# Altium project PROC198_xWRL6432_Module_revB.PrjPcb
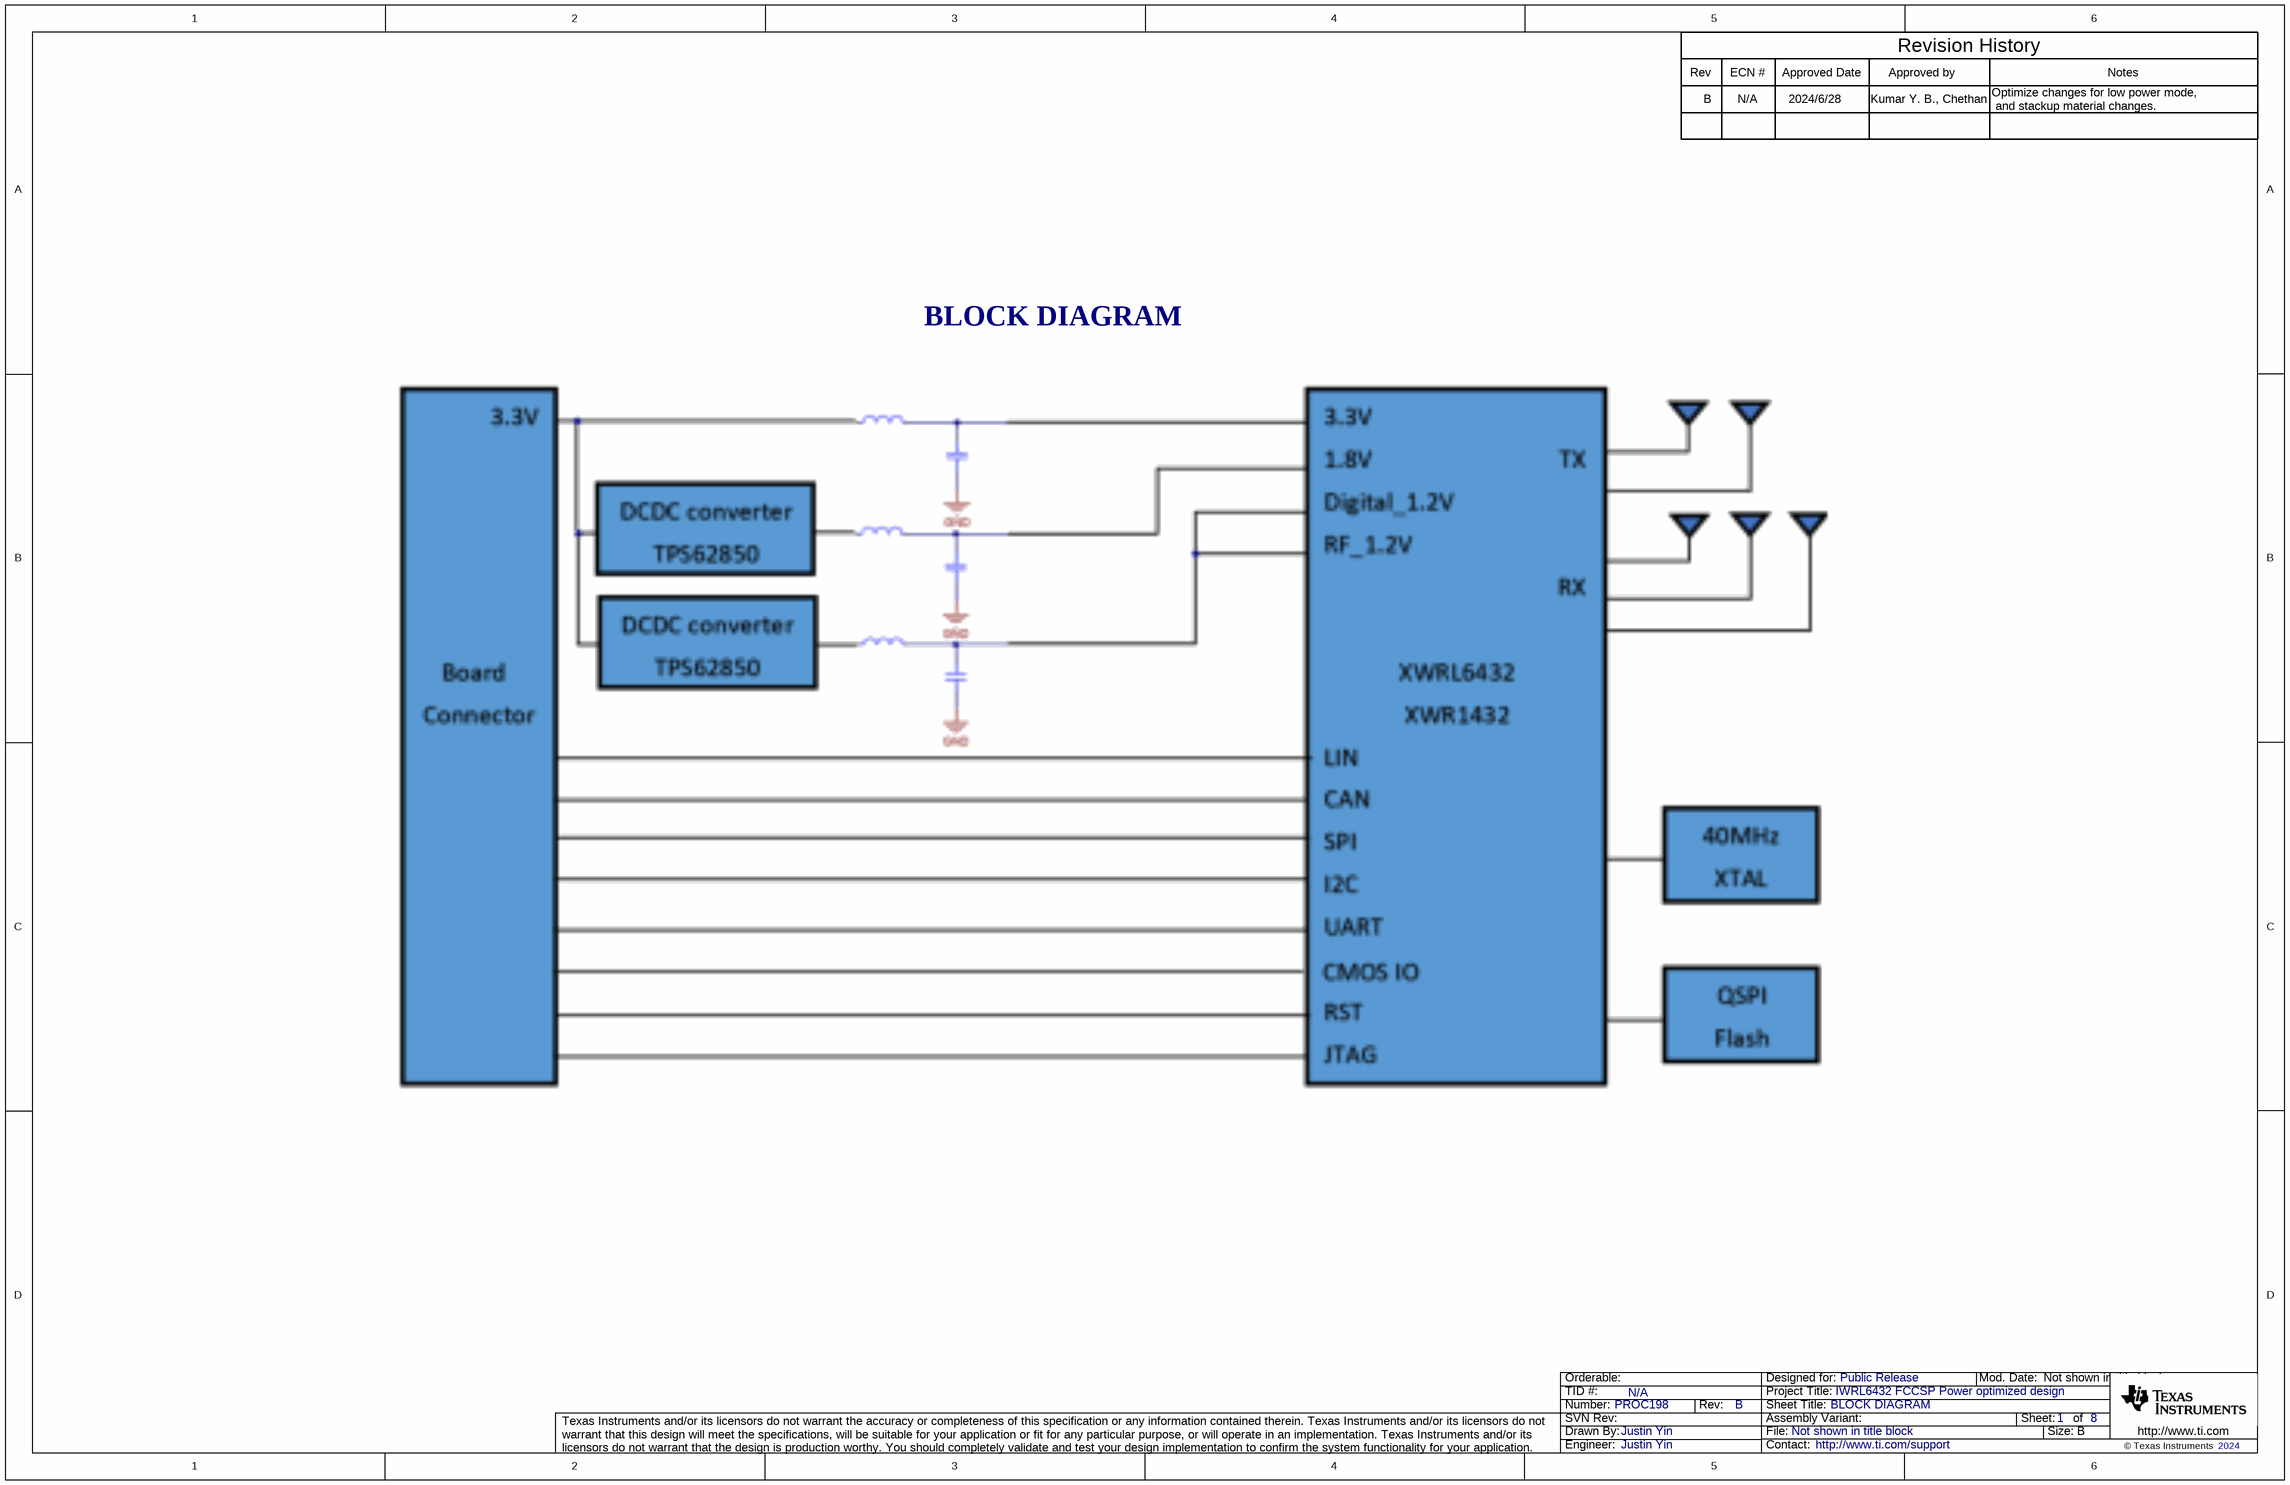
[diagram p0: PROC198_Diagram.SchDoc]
CopyrightYear: 2024; PCB_Layout: Justin Yin; PCB_Rev: B; PRJ_Customer: Public Release; PRJ_Engineer: Justin Yin; PRJ_Number: PROC198; PRJ_Title: IWRL6432 FCCSP Power optimized design; SCH_Rev: B; TechSupport: http://www.ti.com/support; TID: N/A
8 sheets, 117 parts. Net scope: flat (ports and power ports of the same name join across sheets).
Board file: PROC198_PCB.PcbDoc
Sheets:
  PROC198_Diagram.SchDoc
  PROC198_Table_Of_Contents.SchDoc
  PROC198_PWR_Connector.SchDoc
  PROC198_DC_Regulators.SchDoc
  PROC198_xWRL6432_Chip.SchDoc
  PROC198_Decoupling_caps.SchDoc
  PROC198_QSPI_Flash.SchDoc
  PROC198_Hardware.SchDoc

## Sheet PROC198_Diagram.SchDoc: BLOCK DIAGRAM
size 431 x 279 mm; Date: Not shown in title block; ApprovedBy: Not shown in title block; CheckedBy: Not shown in title block; Author: Not shown in title block; CompanyName: Not shown in title block; DrawnBy: Justin Yin; Organization: Not shown in title block; Address1: Not shown in title block; Address2: Not shown in title block; Address3: Not shown in title block; Address4: Not shown in title block; DocumentNumber: 1; Revision: Use project parameter SCH_Rev; SheetNumber: 1; SheetTotal: 8; PageSetup: Record=PageOptions¦CenterHorizontal=True¦CenterVertical=True¦PrintScale=1.00¦XCorrection=1.00¦YCorrection=1.00¦PrintKind=0¦BorderSize=5000000¦LeftOffset=0¦BottomOffset=0¦Orientation=2¦PaperLength=1000¦PaperWidth=1000¦Scale=100¦PaperSource=15¦PrintQuality=600¦MediaType=1¦DitherType=10¦PaperKind=Letter¦PrintScaleMode=1

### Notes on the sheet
- Rev
- B
- ECN #
- N/A
- 2024/6/28
- Approved Date
- Approved by
- Kumar Y. B., Chethan
- Revision History
- Optimize changes for low power mode,
- Notes
- and stackup material changes.
- BLOCK DIAGRAM

## Sheet PROC198_Table_Of_Contents.SchDoc: TABLE OF CONTENTS
size 431 x 279 mm; Date: Not shown in title block; ApprovedBy: Not shown in title block; CheckedBy: Not shown in title block; Author: Not shown in title block; CompanyName: Not shown in title block; DrawnBy: Justin Yin; Engineer: Not shown in title block; Organization: Not shown in title block; Address1: Not shown in title block; Address2: Not shown in title block; Address3: Not shown in title block; Address4: Not shown in title block; DocumentNumber: 2; Revision: Use project parameter SCH_Rev; SheetNumber: 2; SheetTotal: 8; PageSetup: Record=PageOptions¦CenterHorizontal=True¦CenterVertical=True¦PrintScale=1.00¦XCorrection=1.00¦YCorrection=1.00¦PrintKind=0¦BorderSize=5000000¦LeftOffset=0¦BottomOffset=0¦Orientation=2¦PaperLength=1000¦PaperWidth=1000¦Scale=100¦PaperSource=15¦PrintQuality=600¦MediaType=1¦DitherType=10¦PaperKind=Letter¦PrintScaleMode=1
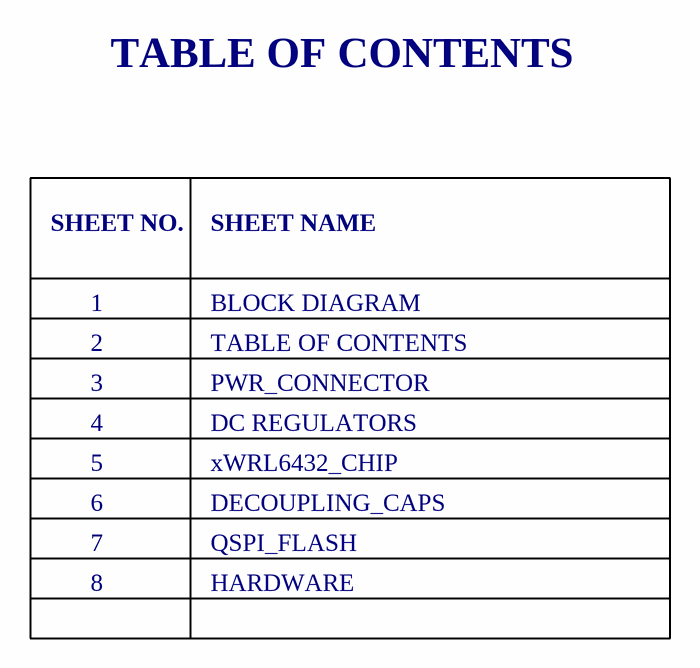
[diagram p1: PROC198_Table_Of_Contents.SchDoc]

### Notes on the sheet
- TABLE OF CONTENTS
- SHEET NO.
- SHEET NAME
- 1
- 2
- 3
- BLOCK DIAGRAM
- PWR_CONNECTOR
- 4
- 5
- DC REGULATORS
- xWRL6432_CHIP
- 7
- 8
- 6
- DECOUPLING_CAPS
- QSPI_FLASH
- HARDWARE

## Sheet PROC198_PWR_Connector.SchDoc: PWR_Connector
size 431 x 279 mm; Date: Not shown in title block; ApprovedBy: Not shown in title block; CheckedBy: Not shown in title block; Author: Not shown in title block; CompanyName: Not shown in title block; DrawnBy: Justin Yin; Engineer: Not shown in title block; Organization: Not shown in title block; Address1: Not shown in title block; Address2: Not shown in title block; Address3: Not shown in title block; Address4: Not shown in title block; DocumentNumber: 3; Revision: Use project parameter SCH_Rev; SheetNumber: 3; SheetTotal: 8; PageSetup: Record=PageOptions¦CenterHorizontal=True¦CenterVertical=True¦PrintScale=1.00¦XCorrection=1.00¦YCorrection=1.00¦PrintKind=0¦BorderSize=5000000¦LeftOffset=0¦BottomOffset=0¦Orientation=2¦PaperLength=1000¦PaperWidth=1000¦Scale=100¦PaperSource=15¦PrintQuality=600¦MediaType=1¦DitherType=10¦PaperKind=Letter¦PrintScaleMode=1
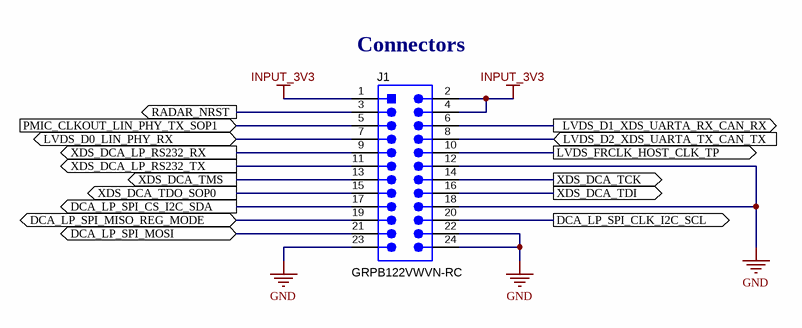
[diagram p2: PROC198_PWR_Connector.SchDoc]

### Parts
J1  GRPB122VWVN-RC  [Sullins_GRPB122VWVN]

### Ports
DCA_LP_SPI_CLK_I2C_SCL (out), DCA_LP_SPI_CS_I2C_SDA (out), DCA_LP_SPI_MISO_REG_MODE (bidir), DCA_LP_SPI_MOSI (bidir), LVDS_D0_LIN_PHY_RX (bidir), LVDS_D1_XDS_UARTA_RX_CAN_RX (out), LVDS_D2_XDS_UARTA_TX_CAN_TX (in), LVDS_FRCLK_HOST_CLK_TP (out), PMIC_CLKOUT_LIN_PHY_TX_SOP1 (in), RADAR_NRST (out), XDS_DCA_LP_RS232_RX (out), XDS_DCA_LP_RS232_TX (out), XDS_DCA_TCK (out), XDS_DCA_TDI (out), XDS_DCA_TDO_SOP0 (out), XDS_DCA_TMS (out)

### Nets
GND: J1.12 J1.18 J1.22 J1.23 J1.24
INPUT_3V3: J1.1 J1.2 J1.4
DCA_LP_SPI_CLK_I2C_SCL: J1.20 ; port DCA_LP_SPI_CLK_I2C_SCL
DCA_LP_SPI_CS_I2C_SDA: J1.17 ; port DCA_LP_SPI_CS_I2C_SDA
DCA_LP_SPI_MISO_REG_MODE: J1.19 ; port DCA_LP_SPI_MISO_REG_MODE
DCA_LP_SPI_MOSI: J1.21 ; port DCA_LP_SPI_MOSI
LVDS_D0_LIN_PHY_RX: J1.7 ; port LVDS_D0_LIN_PHY_RX
LVDS_D1_XDS_UARTA_RX_CAN_RX: J1.6 ; port LVDS_D1_XDS_UARTA_RX_CAN_RX
LVDS_D2_XDS_UARTA_TX_CAN_TX: J1.8 ; port LVDS_D2_XDS_UARTA_TX_CAN_TX
LVDS_FRCLK_HOST_CLK_TP: J1.10 ; port LVDS_FRCLK_HOST_CLK_TP
PMIC_CLKOUT_LIN_PHY_TX_SOP1: J1.5 ; port PMIC_CLKOUT_LIN_PHY_TX_SOP1
RADAR_NRST: J1.3 ; port RADAR_NRST
XDS_DCA_LP_RS232_RX: J1.9 ; port XDS_DCA_LP_RS232_RX
XDS_DCA_LP_RS232_TX: J1.11 ; port XDS_DCA_LP_RS232_TX
XDS_DCA_TCK: J1.14 ; port XDS_DCA_TCK
XDS_DCA_TDI: J1.16 ; port XDS_DCA_TDI
XDS_DCA_TDO_SOP0: J1.15 ; port XDS_DCA_TDO_SOP0
XDS_DCA_TMS: J1.13 ; port XDS_DCA_TMS

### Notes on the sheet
- (near J1) Connectors

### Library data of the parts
J1 = CMP-0054595-1: Header, 1.27mm, 12x2, Gold, TH; Manufacturer: Sullins Connector Solutions; CNHeader: TRUE; Current_A: 1A; Gender: Male; Row_Count: 2; RowSpacing_mm: 1.27; CT: FALSE; Cert_UL: Y

## Sheet PROC198_DC_Regulators.SchDoc: DC_REGULATORS
size 431 x 279 mm; Date: Not shown in title block; ApprovedBy: Not shown in title block; CheckedBy: Not shown in title block; Author: Not shown in title block; CompanyName: Not shown in title block; DrawnBy: Justin Yin; Engineer: Not shown in title block; Organization: Not shown in title block; Address1: Not shown in title block; Address2: Not shown in title block; Address3: Not shown in title block; Address4: Not shown in title block; DocumentNumber: 4; Revision: Use project parameter SCH_Rev; SheetNumber: 4; SheetTotal: 8; PageSetup: Record=PageOptions¦CenterHorizontal=True¦CenterVertical=True¦PrintScale=1.00¦XCorrection=1.00¦YCorrection=1.00¦PrintKind=0¦BorderSize=5000000¦LeftOffset=0¦BottomOffset=0¦Orientation=2¦PaperLength=1000¦PaperWidth=1000¦Scale=100¦PaperSource=15¦PrintQuality=600¦MediaType=1¦DitherType=10¦PaperKind=Letter¦PrintScaleMode=1
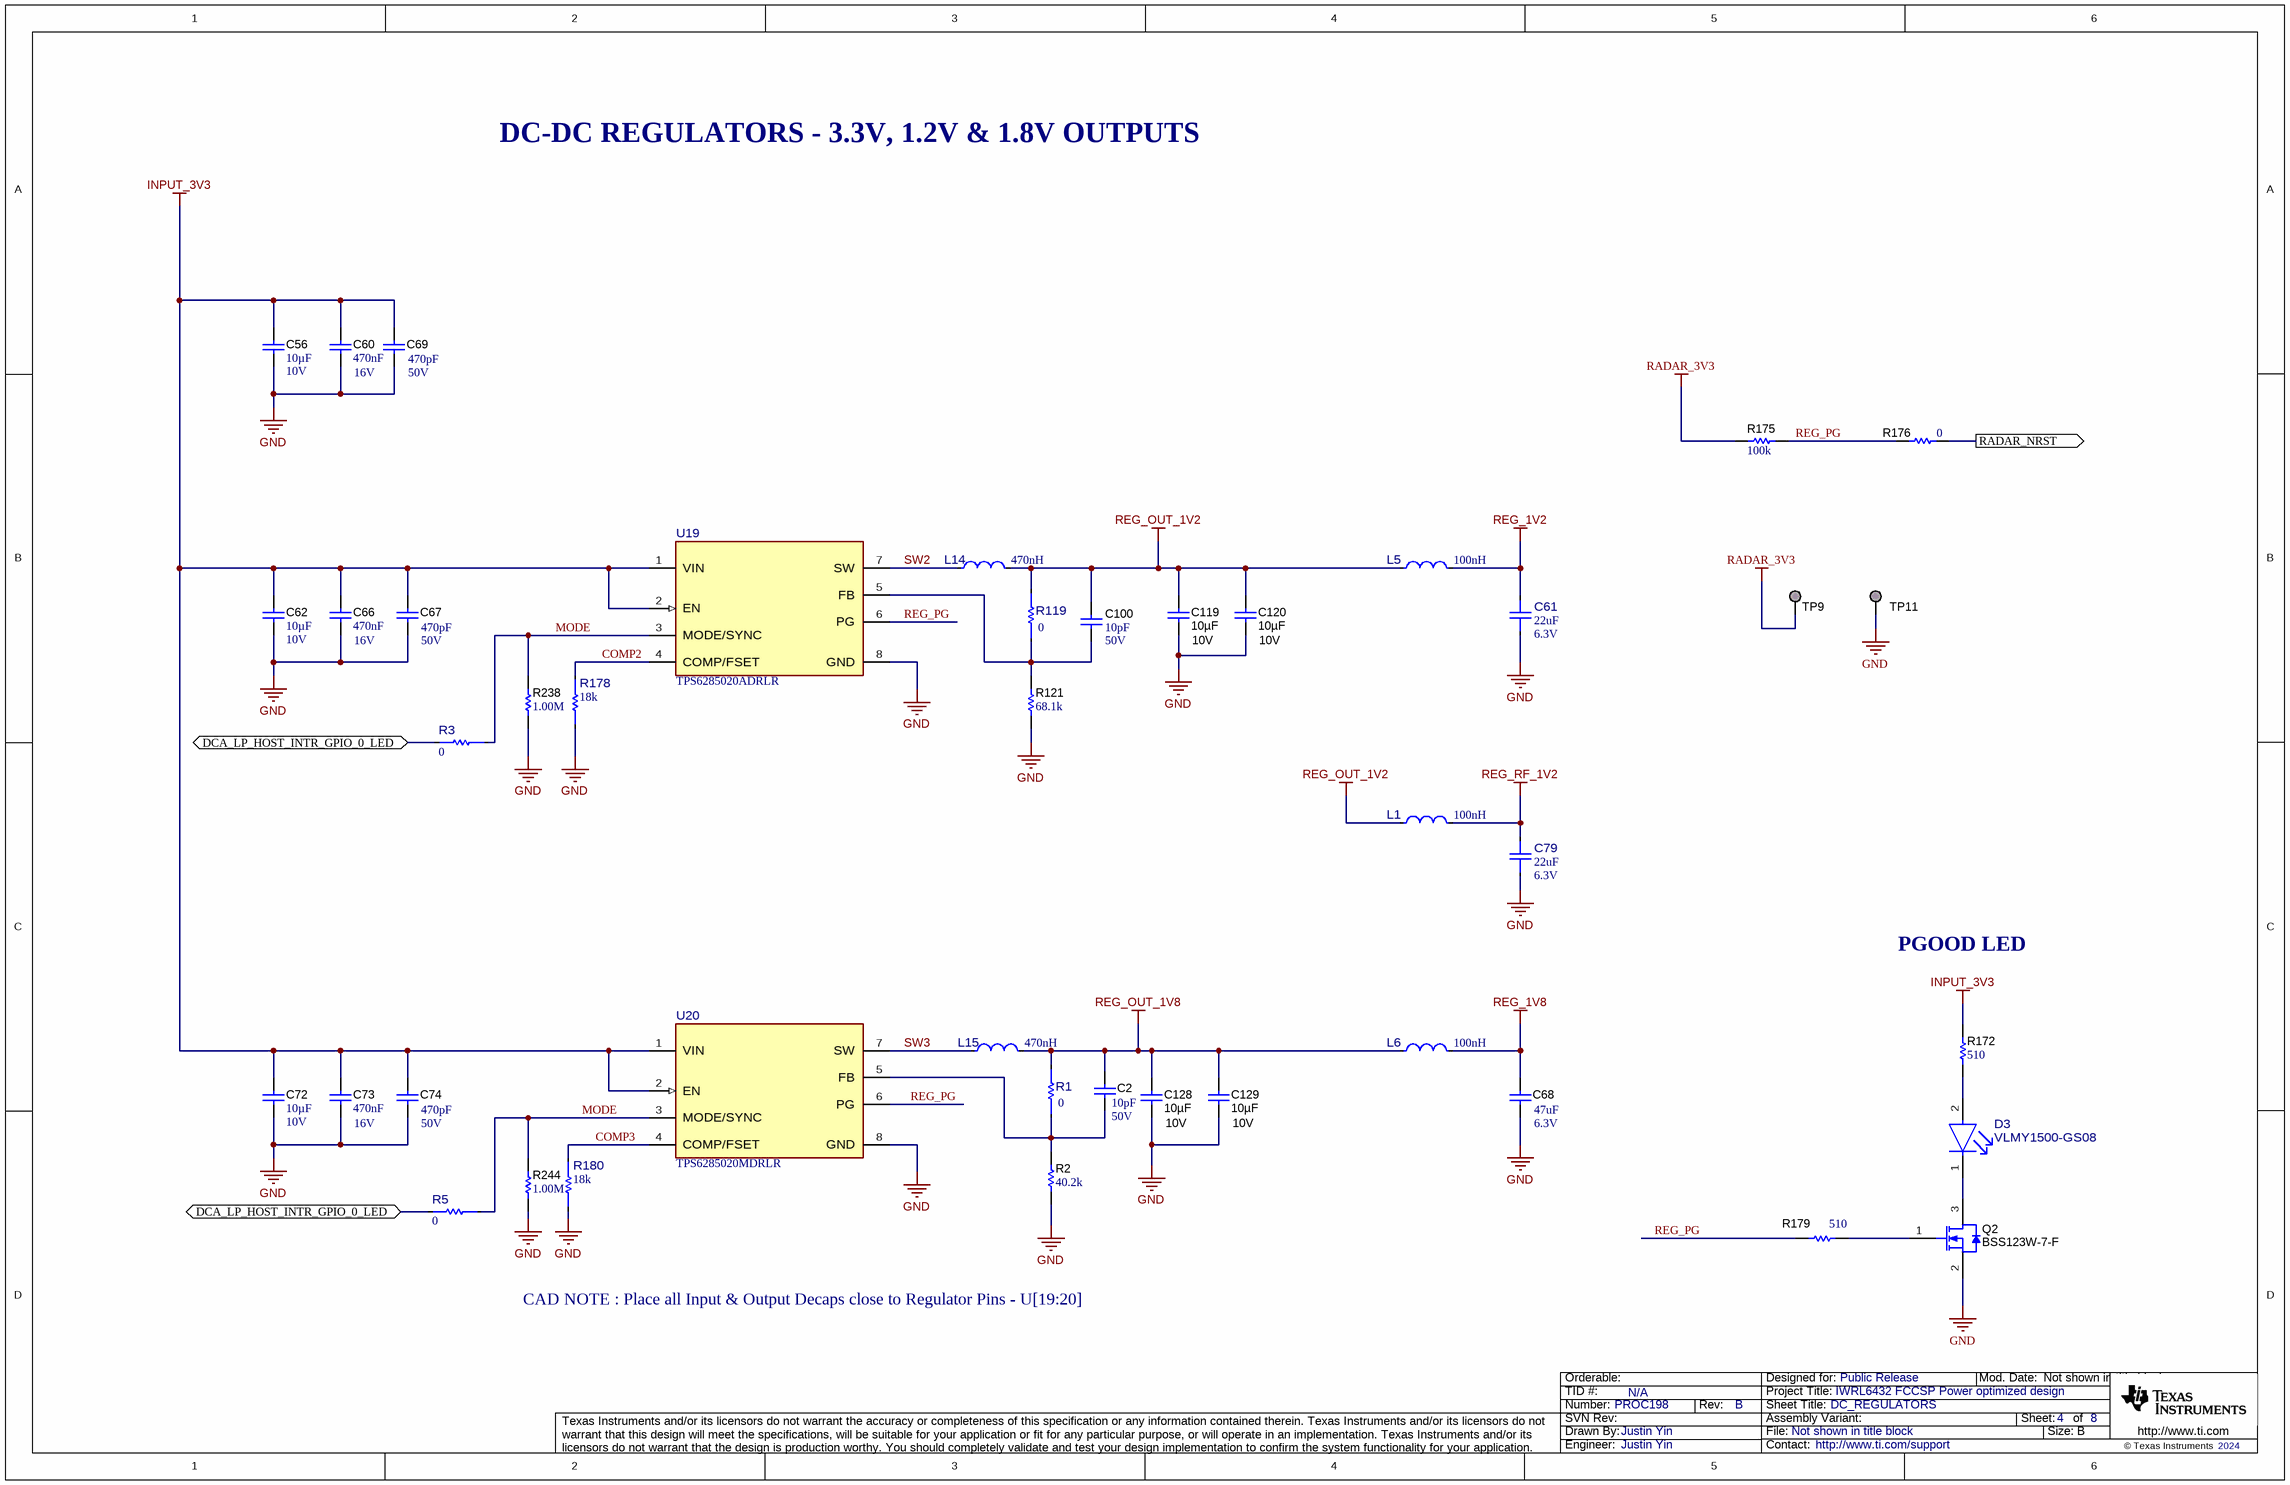
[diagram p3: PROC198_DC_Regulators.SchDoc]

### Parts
C2  VDC_V: 50V  ValueDisplayed: 10pF  [0402L]  (hidden comment: GRM1555C1H100JA01D)
C56  Cap_F: 10µF  VDC_V: 10V  [0603_HV]  (hidden comment: GRM188Z71A106MA73D)
C60  Value2: 16V  Cap_F: 470nF  [0603L]  (hidden comment: GRM188R71C474KA88D)
C61  VDC_V: 6.3V  ValueDisplayed: 22uF  [FP-GRM31CR70J226ME19K_1206-MFG]  (hidden comment: GRM31CR70J226ME19K)
C62  Cap_F: 10µF  VDC_V: 10V  [0603_HV]  (hidden comment: GRM188Z71A106MA73D)
C66  Value2: 16V  Cap_F: 470nF  [0603L]  (hidden comment: GRM188R71C474KA88D)
C67  Value2: 50V  ValueDisplayed: 470pF  [0402L]  (hidden comment: GRM1555C1H471JA01D)
C68  Value2: 6.3V  ValueDisplayed: 47uF  [1206_180]  (hidden comment: GRM31CR60J476ME19L)
C69  Value2: 50V  ValueDisplayed: 470pF  [0402L]  (hidden comment: GRM1555C1H471JA01D)
C72  Cap_F: 10µF  VDC_V: 10V  [0603_HV]  (hidden comment: GRM188Z71A106MA73D)
C73  Value2: 16V  Cap_F: 470nF  [0603L]  (hidden comment: GRM188R71C474KA88D)
C74  Value2: 50V  ValueDisplayed: 470pF  [0402L]  (hidden comment: GRM1555C1H471JA01D)
C79  VDC_V: 6.3V  ValueDisplayed: 22uF  [FP-GRM31CR70J226ME19K_1206-MFG]  (hidden comment: GRM31CR70J226ME19K)
C100  VDC_V: 50V  ValueDisplayed: 10pF  [0402L]  (hidden comment: GRM1555C1H100JA01D)
C119  Value2: 10V  Cap_F: 10µF  [0603L]  (hidden comment: GRM188Z71A106MA73D)
C120  Value2: 10V  Cap_F: 10µF  [0603L]  (hidden comment: GRM188Z71A106MA73D)
C128  Value2: 10V  Cap_F: 10µF  [0603L]  (hidden comment: GRM188Z71A106MA73D)
C129  Value2: 10V  Cap_F: 10µF  [0603L]  (hidden comment: GRM188Z71A106MA73D)
D3  VLMY1500-GS08  [FP-VLMY1500-GS08_0402-MFG]
L1  Ind_H: 100nH  [FP-LQM2MPZR10MJHL_0806 (2016)-MFG]  (hidden comment: LQM2MPZR10MJHL)
L5  Ind_H: 100nH  [FP-LQM2MPZR10MJHL_0806 (2016)-MFG]  (hidden comment: LQM2MPZR10MJHL)
L6  Ind_H: 100nH  [FP-LQM2MPZR10MJHL_0806 (2016)-MFG]  (hidden comment: LQM2MPZR10MJHL)
L14  Ind_H: 470nH  [FP-DFE201210U-R47M=P2_0805 (2012)-MFG]  (hidden comment: DFE201210U-R47M=P2)
L15  Ind_H: 470nH  [FP-DFE201210U-R47M=P2_0805 (2012)-MFG]  (hidden comment: DFE201210U-R47M=P2)
Q2  BSS123W-7-F  [SOT-323]
R1  value 0  [FP-RC0402JR-070RP_0402-MFG]  (hidden comment: RC0402JR-070RP)
R2  ValueDisplayed: 40.2k  [0402L]  (hidden comment: CRCW040240K2FKED)
R3  value 0  [FP-RC0402JR-070RP_0402-MFG]  (hidden comment: RC0402JR-070RP)
R5  value 0  [FP-RC0402JR-070RP_0402-MFG]  (hidden comment: RC0402JR-070RP)
R119  value 0  [FP-RC0402JR-070RP_0402-MFG]  (hidden comment: RC0402JR-070RP)
R121  ValueDisplayed: 68.1k  [0402L]  (hidden comment: RC0402FR-0768K1L)
R172  ValueDisplayed: 510  [0402L]  (hidden comment: ERJ-2RKF5100X)
R175  value 100k  [0201L]  (hidden comment: CRCW0201100KFKED)
R176  Res_ohm: 0  [FP-RC0201JR-070RL_0201 (0603 Metric)-IPC_C]  (hidden comment: RC0201JR-070RL)
R178  value 18k  [FP-CRCW040218K0FKEDC_0402-MFG]  (hidden comment: CRCW040218K0FKEDC)
R179  ValueDisplayed: 510  [0402L]  (hidden comment: ERJ-2RKF5100X)
R180  value 18k  [FP-CRCW040218K0FKEDC_0402-MFG]  (hidden comment: CRCW040218K0FKEDC)
R238  ValueDisplayed: 1.00M  [0402]  (hidden comment: RC0402FR-071ML)
R244  ValueDisplayed: 1.00M  [0402]  (hidden comment: RC0402FR-071ML)
TP9  TESTPOINT  [TP_25MIL-SMT]  (value not drawn)  (no BOM)
TP11  TESTPOINT  [TP_25MIL-SMT]  (value not drawn)  (no BOM)
U19  TPS6285020ADRLR  [DRL0008A-MFG]
U20  TPS6285020MDRLR  [DRL0008A-MFG]

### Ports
DCA_LP_HOST_INTR_GPIO_0_LED (bidir), RADAR_NRST (out)

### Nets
GND: C56.2 C60.2 C61.1 C62.2 C66.2 C67.2 C68.1 C69.2 C72.2 C73.2 C74.2 C79.1 C119.2 C120.2 C128.2 C129.2 Q2.2(S) R2.1 R121.1 R178.2 R180.2 R238.1 R244.1 TP11.1 U19.8(GND) U20.8(GND)
INPUT_3V3: C56.1 C60.1 C62.1 C66.1 C67.1 C69.1 C72.1 C73.1 C74.1 R172.1 U19.1(VIN) U19.2(EN) U20.1(VIN) U20.2(EN)
RADAR_3V3: R175.1 TP9.1
REG_1V2: C61.2 L5.2
REG_1V8: C68.2 L6.2
REG_OUT_1V2: C100.1 C119.1 C120.1 L1.1 L5.1 L14.2 R119.2
REG_OUT_1V8: C2.1 C128.1 C129.1 L6.1 L15.2 R1.2
REG_RF_1V2: C79.2 L1.2
COMP2: R178.1 U19.4(COMP/FSET)
COMP3: R180.1 U20.4(COMP/FSET)
DCA_LP_HOST_INTR_GPIO_0_LED: R3.2 R5.2 ; port DCA_LP_HOST_INTR_GPIO_0_LED
MODE: R3.1 R5.1 R238.2 R244.2 U19.3(MODE/SYNC) U20.3(MODE/SYNC)
RADAR_NRST: R176.1 ; port RADAR_NRST
REG_PG: R175.2 R176.2 R179.2 U19.6(PG) U20.6(PG)
SW2: L14.1 U19.7(SW)
SW3: L15.1 U20.7(SW)
NetC2_2: C2.2 R1.1 R2.2 U20.5(FB)
NetC100_2: C100.2 R119.1 R121.2 U19.5(FB)
NetD3_1: D3.1(CATHODE) Q2.3(D)
NetD3_2: D3.2(ANODE) R172.2
NetQ2_1: Q2.1(G) R179.1

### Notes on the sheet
- DC-DC REGULATORS - 3.3V, 1.2V & 1.8V OUTPUTS
- PGOOD LED
- CAD NOTE : Place all Input & Output Decaps close to Regulator Pins - U[19:20]

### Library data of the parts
C2 C100 = CMP-0006408-2: CAP, CERM, 10 pF, 50 V, +/- 5%, C0G/NP0, 0402; Manufacturer: MuRata; TaMin_C: -55°C; Polarized: N; SizeAreaWB_mm2: 3; Value1: Unknown; U/M: EA; Value: 10pF; TaMax_C: 125°C; SizeZ_mm: 0.6; SizeX_mm: 1; SizeY_mm: 0.5; Cap_Case: 0402; AEC Category: Q200
C56 C62 C72 C119 C120 C128 C129 = CMP-0007497-5: CAP, CERM, 10 uF, 10 V, +/- 20%, X7R, 0603; Manufacturer: MuRata; TaMin_C: -55°C; Polarized: N; SizeAreaWB_mm2: 4.68; Value1: Unknown; U/M: EA; Value: 10uF; TaMax_C: 125°C; SizeZ_mm: 1; SizeX_mm: 1.6; SizeY_mm: 0.8; Cap_Case: 0603; SizeArea_mm2: 1.28; AEC Category: Q200
C60 C66 C73 = CMP-0007398-4: CAP, CERM, 0.47 uF, 16 V, +/- 10%, X7R, 0603; Manufacturer: MuRata; TaMin_C: -55°C; Polarized: N; SizeAreaWB_mm2: 4.68; Value1: Unknown; U/M: EA; Value: 0.47uF; TaMax_C: 125°C; SizeZ_mm: 1; SizeX_mm: 1.6; SizeY_mm: 0.8; Cap_Case: 0603; SizeArea_mm2: 1.28; AEC Category: Q200
C61 C79 = CMP-0092150-1: Chip Multilayer Ceramic Capacitors for General Purpose, 1206, 22uF, X7R, 15%, 20%, 6.3V; Manufacturer: Murata; SizeZ_mm: 1.8mm; AEC Qualified: No; Value: 22µF
C67 C69 C74 = CMP-0006470-2: CAP, CERM, 470 pF, 50 V, +/- 5%, C0G/NP0, 0402; Manufacturer: MuRata; TaMin_C: -55°C; Polarized: N; SizeAreaWB_mm2: 3; Value1: Unknown; U/M: EA; Value: 470pF; TaMax_C: 125°C; SizeZ_mm: 0.6; SizeX_mm: 1; SizeY_mm: 0.5; Cap_Case: 0402; AEC Category: Q200
C68 = CMP-0008940-2: CAP, CERM, 47 uF, 6.3 V, +/- 20%, X5R, 1206; Manufacturer: MuRata; TaMin_C: -55°C; ESR_ohm: 3m; Polarized: N; SizeAreaWB_mm2: 10.92; Value1: 0.003 ohm; U/M: EA; Value: 47uF; TaMax_C: 85°C; SizeZ_mm: 1.8; SizeX_mm: 3.2; SizeY_mm: 1.6; Cap_Case: 1206; SizeArea_mm2: 5.12; Cap_F: 47µF; AEC Category: Q200
D3 = CMP-0090807-1: LED Uni-Color Yellow 588nm 2-Pin Chip 0402(1006Metric) T/R; Manufacturer: Vishay; AEC Qualified: No; Led Orientation: Top View; SizeZ_mm: 0.35mm; TaMin_C: -30°C; Angle: 130°; LambdaD: 590nm; Power_TotalModule: 75mW; TaMax_C: +85°C; Forward Current: 20mA; Vr_V: 5V; Vf_V: 2V; Luminous Intensity: 90mcd
L1 L5 L6 = CMP-0095018-1: 100nH Shielded Multilayer Inductor 4A 19mOhm Max 0806 (2016 Metric); Manufacturer: Murata; Tolerance_%: 20%; Self Resonant Frequency: 200MHz; Test Frequency: 1MHz; Irms: 4000mA; Shrouded: true; SizeZ_mm: 1.2mm; Value: 0.1uH; AEC Grade: Grade 1; DCR_ohm: 19m; Material: Ferrite; AEC Qualified: Yes
L14 L15 = CMP-0092096-1: 470nH Shielded Wirewound Inductor 3A 42mOhm Max 0805 (2012 Metric); Manufacturer: Murata; DCR_ohm: 42m; Shrouded: true; SizeZ_mm: 1mm; Value: 0.47uH; Tolerance_%: 20%; Test Frequency: 1MHz; Isat: 4.4A; AEC Qualified: No; Material: Metal Alloy
Q2 = CMP-0000948-2: MOSFET, N-CH, 100 V, 0.17 A, SOT-323; Alternate Manufacturer: None; Manufacturer: Diodes Inc.; SizeZ_mm: 1.1; ChType: N; Value1: 1; VdsMax_V: 100V; SizeX_mm: 2.2; Vgs_V: 20V; Value: 100V; Rdson45_ohm: 10; SizeArea_mm2: 4.84; AEC Category: Q101; IdsMax_A: 170mA; SizeAreaWB_mm2: 10.24; U/M: EA
R1 R3 R5 R119 = CMP-0093147-1: Res Jumper Thick Film 0402 0 Ohm 5% 1/16W Molded SMD Paper T/R; Manufacturer: Yageo; AEC Qualified: No; Power_W: 63mW; SizeZ_mm: 0.4mm; VDC_V: 50V
R2 = CMP-0026367-2: RES, 40.2 k, 1%, 0.063 W, AEC-Q200 Grade 0, 0402; Manufacturer: Vishay-Dale; Power_W: 63mW; TempCo: 100 ppm/C; Value_Code: 40k2; Value: 40.2k; EIA_Code: E96; SizeX_mm: 1; SizeY_mm: 0.5; SizeZ_mm: 0.6; Value2: 0.063W; AEC Qualified: Y; VDC_V: 50V; AEC Category: Q200; AEC Grade: 0
R121 = CMP-0078786-1: RES, 68.1 k, 1%, 0.063 W, 0402; Manufacturer: Yageo America; Value_Code: 68k1; SizeArea_mm2: 0.5; AEC Qualified: N; AEC Category: Q200; Value: 68.1k; SizeZ_mm: 0.6; EIA_Code: E96; TempCo: 100 ppm/C; Power_W: 63mW; VDC_V: 50V; Value2: 0.063W; SizeX_mm: 1
R172 R179 = CMP-0026704-1: RES, 510, 1%, 0.1 W, 0402; Manufacturer: Panasonic; Power_W: 100mW; TempCo: 100 ppm/C; Value_Code: 510R; U/M: EA; Value: 510; SizeX_mm: 1; SizeY_mm: 0.5; SizeZ_mm: 0.6; Value2: 0.1W; VDC_V: 50V; AEC Category: Q200
R175 = CMP-0027261-3: RES, 100 k, 1%, 0.05 W, 0201; Manufacturer: Vishay-Dale; AEC Category: Q200; AEC Qualified: N; EIA_Code: E96; Power_W: 50mW; SizeArea_mm2: 0.18; SizeX_mm: 0.6; SizeY_mm: 0.3; SizeZ_mm: 0.26; TempCo: 100 ppm/C; Value2: 0.05W; VDC_V: 30V
R176 = CMP-0086442-2: RES SMD 0 OHM JUMPER 1/20W 0201; Manufacturer: Yageo; AEC Qualified: No; Power_W: 50mW; SizeZ_mm: 0.26mm; TempCo: 200ppm/°C; Tolerance_%: 5%; VDC_V: 25V
R178 R180 = CMP-0094741-1: Res Thick Film 0402 18K Ohm 1% 1/16W ±100ppm/°C Molded SMD Paper T/R; Manufacturer: Vishay; VDC_V: 50V; SizeZ_mm: 0.35mm; AEC Qualified: No; Power_W: 63mW
R238 R244 = CMP-0026727-1: RES, 1.00 M, 1%, 0.063 W, 0402; Manufacturer: Yageo America; Power_W: 63mW; TempCo: 100 ppm/C; Value_Code: 1M00; U/M: EA; Value: 1.00Meg; EIA_Code: E96; Res_ohm: 1M; SizeX_mm: 1; SizeY_mm: 0.5; SizeZ_mm: 0.6; Value2: 0.063W; AEC Category: Q200
TP9 TP11 = CMP-0078143-4: TEST POINT.  No entry in BOM.
U19 = CMP-0120067-1: 2.7-V to 6-V, 2-A Step-Down Converter in SOT583 Package; Manufacturer: Texas Instruments; SizeZ_mm: 0.6mm; AEC Qualified: No; Max Duty Cycle: 100%; Max Supply Voltage: 6V; Min Supply Voltage: 2.7V; Nominal Supply Current: 17uA; Number Of Outputs: 1; Output Type: AdjustableProgrammable; Output Voltage: 0.6-5.5V; Standoff Height: 0mm; Switching Frequency: 1.8-4MHz; Switching Topology: Buck; TJmax_C: +150°C
U20 = CMP-0120069-1: 2.7-V to 6-V, 2-A Step-Down Converter in SOT583 Package; Manufacturer: Texas Instruments; SizeZ_mm: 0.6mm; AEC Qualified: No; Max Duty Cycle: 100%; Max Supply Voltage: 6V; Min Supply Voltage: 2.7V; Nominal Supply Current: 17uA; Number Of Outputs: 1; Output Type: AdjustableProgrammable; Output Voltage: 0.6-5.5V; Standoff Height: 0mm; Switching Frequency: 1.8-4MHz; Switching Topology: Buck; TJmax_C: +150°C

## Sheet PROC198_xWRL6432_Chip.SchDoc: xWRL6432_CHIP
size 431 x 279 mm; Date: Not shown in title block; ApprovedBy: Not shown in title block; CheckedBy: Not shown in title block; Author: Not shown in title block; CompanyName: Not shown in title block; DrawnBy: Justin Yin; Engineer: Not shown in title block; Organization: Not shown in title block; Address1: Not shown in title block; Address2: Not shown in title block; Address3: Not shown in title block; Address4: Not shown in title block; DocumentNumber: 5; Revision: Use project parameter SCH_Rev; SheetNumber: 5; SheetTotal: 8; PageSetup: Record=PageOptions¦CenterHorizontal=True¦CenterVertical=True¦PrintScale=1.00¦XCorrection=1.00¦YCorrection=1.00¦PrintKind=0¦BorderSize=5000000¦LeftOffset=0¦BottomOffset=0¦Orientation=2¦PaperLength=1000¦PaperWidth=1000¦Scale=100¦PaperSource=15¦PrintQuality=600¦MediaType=1¦DitherType=10¦PaperKind=Letter¦PrintScaleMode=1
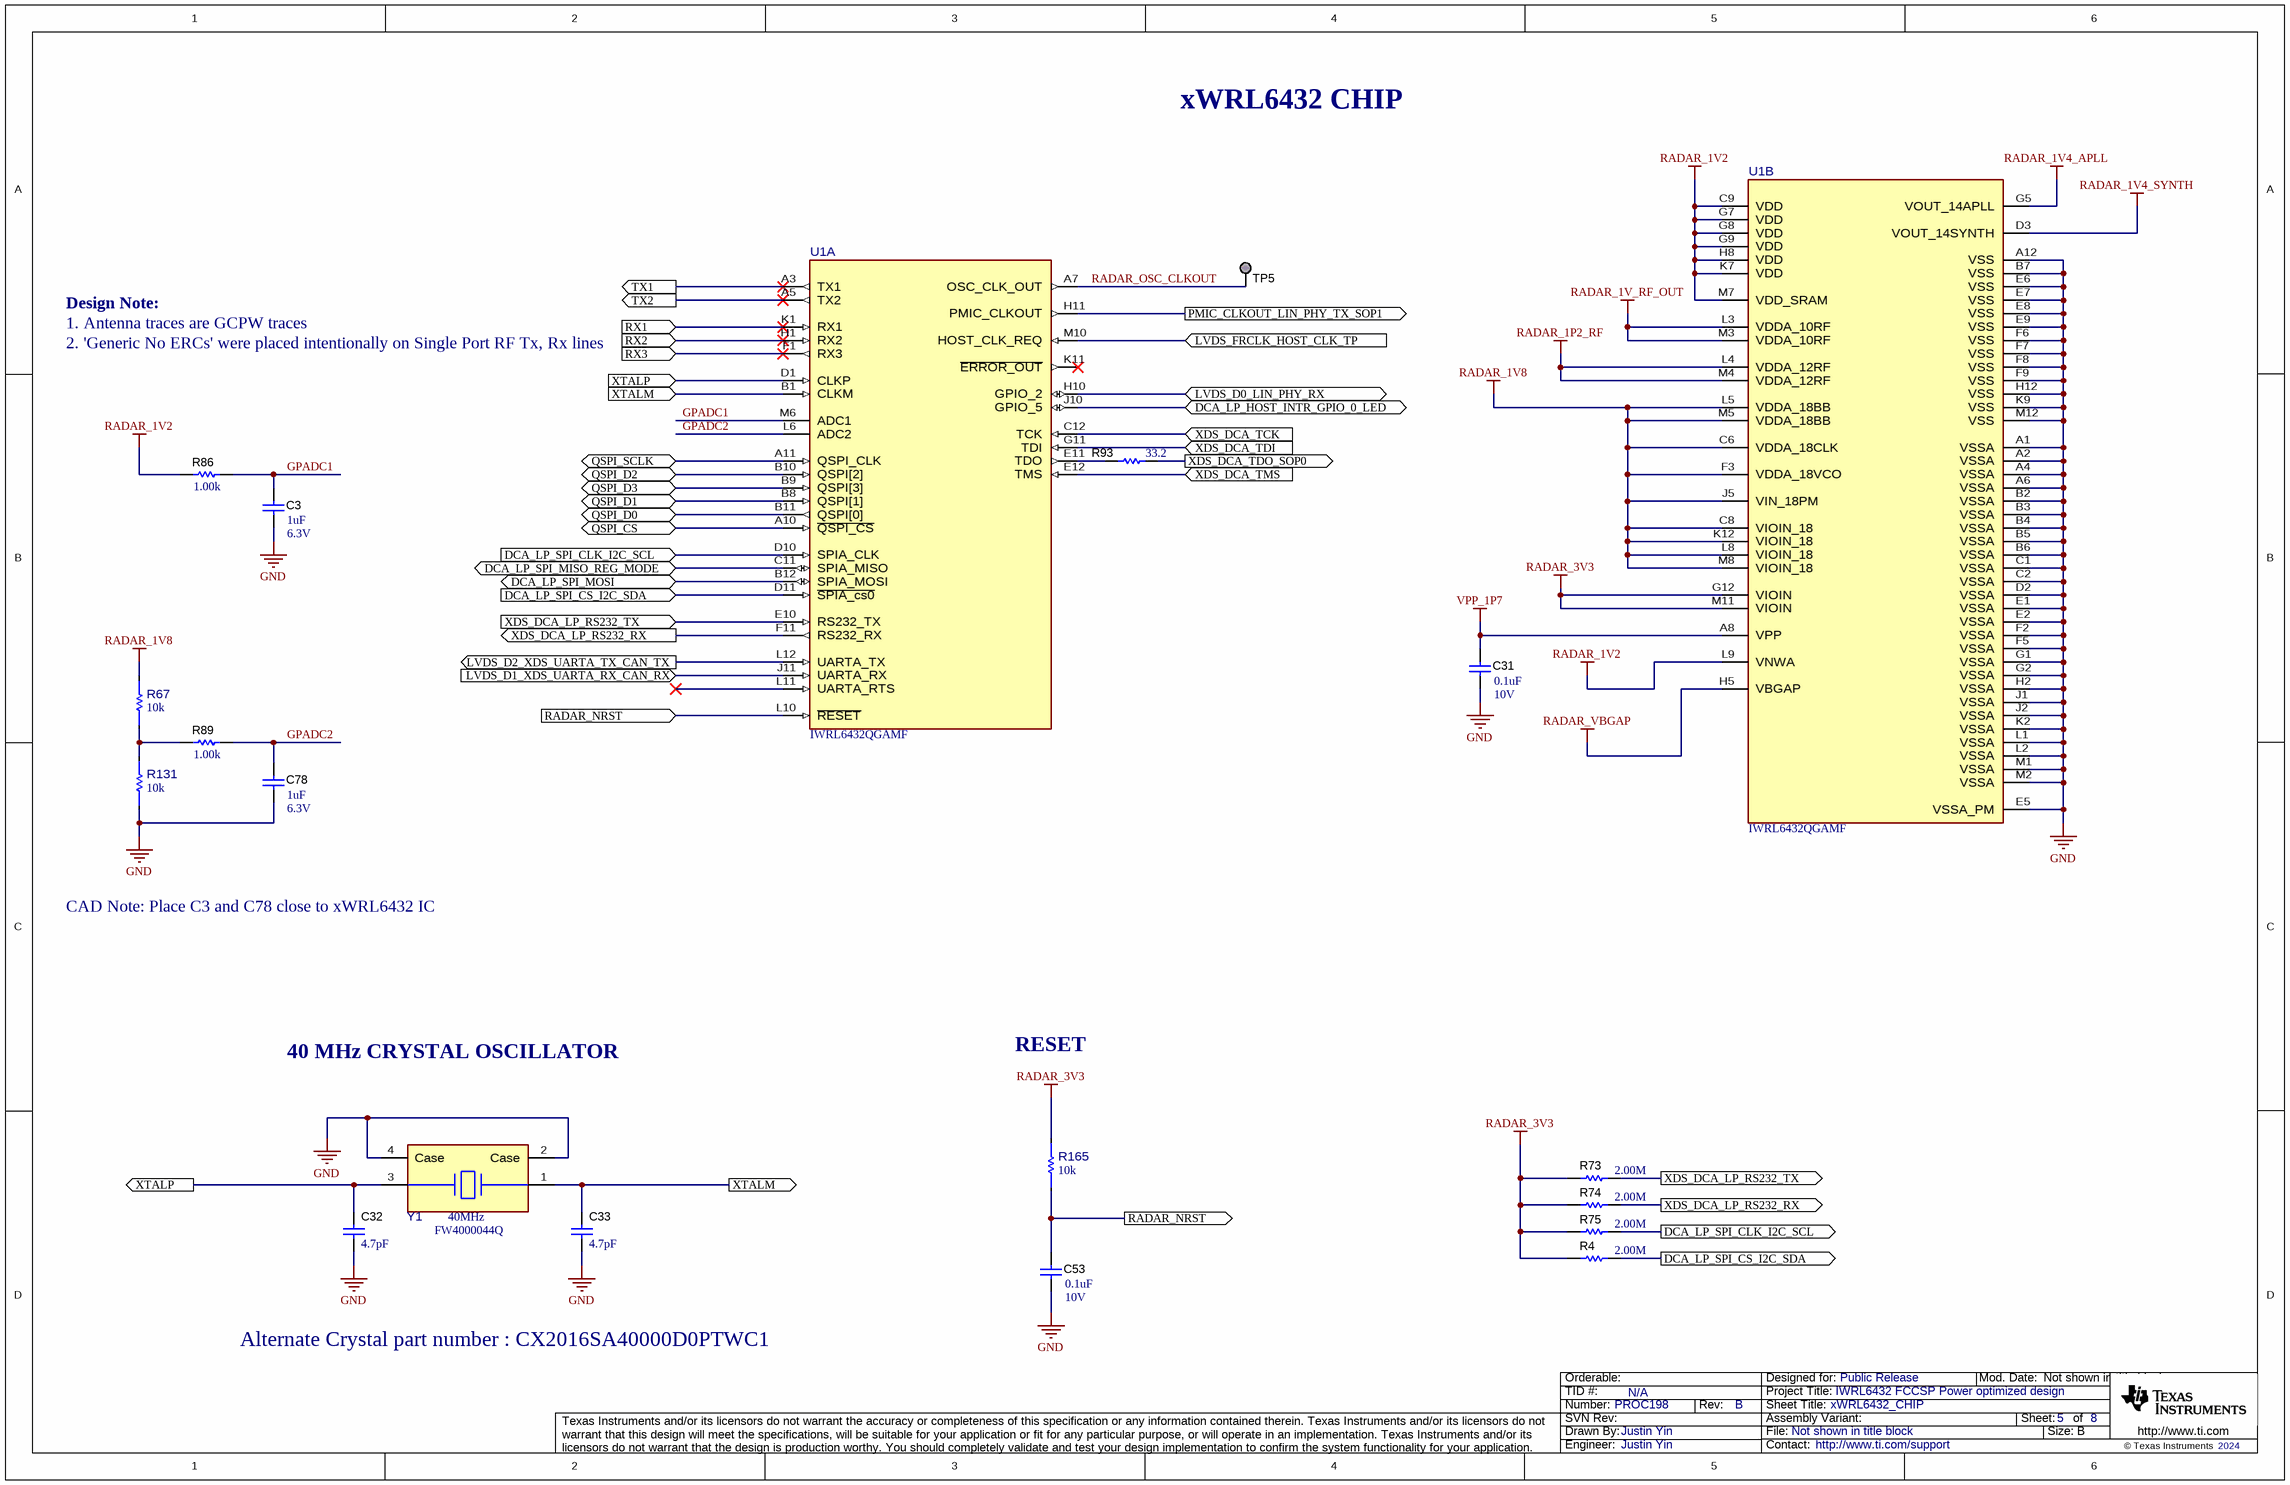
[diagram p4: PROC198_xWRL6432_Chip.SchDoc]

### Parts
C3  VDC_V: 6.3V  ValueDisplayed: 1uF  [0201_033]  (hidden comment: GRM033R60J105MEA2D)
C31  Value2: 10V  ValueDisplayed: 0.1uF  [0201]  (hidden comment: GRM033C71A104KE14D)
C32  ValueDisplayed: 4.7pF  [0402L]  (hidden comment: GJM1555C1H4R7BB01D)
C33  ValueDisplayed: 4.7pF  [0402L]  (hidden comment: GJM1555C1H4R7BB01D)
C53  Value2: 10V  ValueDisplayed: 0.1uF  [0201]  (hidden comment: GRM033C71A104KE14D)
C78  VDC_V: 6.3V  ValueDisplayed: 1uF  [0201_033]  (hidden comment: GRM033R60J105MEA2D)
R4  ValueDisplayed: 2.00M  [0402]  (hidden comment: CRCW04022M00FKED)
R67  Res_ohm: 10k  [FP-ERJ-1RHD1002C_0201-MFG]  (hidden comment: ERJ-1RHD1002C)
R73  ValueDisplayed: 2.00M  [0402]  (hidden comment: CRCW04022M00FKED)
R74  ValueDisplayed: 2.00M  [0402]  (hidden comment: CRCW04022M00FKED)
R75  ValueDisplayed: 2.00M  [0402]  (hidden comment: CRCW04022M00FKED)
R86  ValueDisplayed: 1.00k  [0201]  (hidden comment: CRCW02011K00FKED)
R89  ValueDisplayed: 1.00k  [0201]  (hidden comment: CRCW02011K00FKED)
R93  ValueDisplayed: 33.2  [0201_Silk]  (hidden comment: CRCW020133R2FNED)
R131  Res_ohm: 10k  [FP-ERJ-1RHD1002C_0201-MFG]  (hidden comment: ERJ-1RHD1002C)
R165  Res_ohm: 10k  [FP-ERJ-1RHD1002C_0201-MFG]  (hidden comment: ERJ-1RHD1002C)
TP5  TESTPOINT  [TP_25MIL-SMT]  (value not drawn)  (no BOM)
U1  IWRL6432QGAMF  [AMF0102A-MFG]  (parts A,B of 2)
Y1  Frequency_Fixed: 40MHz  [FP-FW4000044Q_4-SMD-2.0x1.6mm-MFG]  (hidden comment: FW4000044Q)

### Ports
DCA_LP_HOST_INTR_GPIO_0_LED (bidir), DCA_LP_SPI_CLK_I2C_SCL (in), DCA_LP_SPI_CLK_I2C_SCL (out), DCA_LP_SPI_CS_I2C_SDA (in), DCA_LP_SPI_CS_I2C_SDA (out), DCA_LP_SPI_MISO_REG_MODE (bidir), DCA_LP_SPI_MOSI (bidir), LVDS_D0_LIN_PHY_RX (bidir), LVDS_D1_XDS_UARTA_RX_CAN_RX (in), LVDS_D2_XDS_UARTA_TX_CAN_TX (out), LVDS_FRCLK_HOST_CLK_TP (in), PMIC_CLKOUT_LIN_PHY_TX_SOP1 (out), QSPI_CS (bidir), QSPI_D0 (bidir), QSPI_D1 (bidir), QSPI_D2 (bidir), QSPI_D3 (bidir), QSPI_SCLK (bidir), RADAR_NRST (in), RADAR_NRST (out), RX1 (in), RX2 (in), RX3 (in), TX1 (out), TX2 (out), XDS_DCA_LP_RS232_RX (out), XDS_DCA_LP_RS232_TX (in), XDS_DCA_LP_RS232_TX (out), XDS_DCA_TCK (in), XDS_DCA_TDI (in), XDS_DCA_TDO_SOP0 (out), XDS_DCA_TMS (in), XTALM (in), XTALM (out), XTALP (in), XTALP (out)

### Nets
GND: C3.2 C31.1 C32.1 C33.1 C53.1 C78.2 R131.1 U1.A1(VSSA) U1.A2(VSSA) U1.A4(VSSA) U1.A6(VSSA) U1.A12(VSS) U1.B2(VSSA) U1.B3(VSSA) U1.B4(VSSA) U1.B5(VSSA) U1.B6(VSSA) U1.B7(VSS) U1.C1(VSSA) U1.C2(VSSA) U1.D2(VSSA) U1.E1(VSSA) U1.E2(VSSA) U1.E5(VSSA_PM) U1.E6(VSS) U1.E7(VSS) U1.E8(VSS) U1.E9(VSS) U1.F2(VSSA) U1.F5(VSSA) U1.F6(VSS) U1.F7(VSS) U1.F8(VSS) U1.F9(VSS) U1.G1(VSSA) U1.G2(VSSA) U1.H2(VSSA) U1.H12(VSS) U1.J1(VSSA) U1.J2(VSSA) U1.K2(VSSA) U1.K9(VSS) U1.L1(VSSA) U1.L2(VSSA) U1.M1(VSSA) U1.M2(VSSA) U1.M12(VSS) Y1.2(Case) Y1.4(Case)
RADAR_1P2_RF: U1.L4(VDDA_12RF) U1.M4(VDDA_12RF)
RADAR_1V2: R86.1 U1.C9(VDD) U1.G7(VDD) U1.G8(VDD) U1.G9(VDD) U1.H8(VDD) U1.K7(VDD) U1.L9(VNWA) U1.M7(VDD_SRAM)
RADAR_1V4_APLL: U1.G5(VOUT_14APLL)
RADAR_1V4_SYNTH: U1.D3(VOUT_14SYNTH)
RADAR_1V8: R67.2 U1.C6(VDDA_18CLK) U1.C8(VIOIN_18) U1.F3(VDDA_18VCO) U1.J5(VIN_18PM) U1.K12(VIOIN_18) U1.L5(VDDA_18BB) U1.L8(VIOIN_18) U1.M5(VDDA_18BB) U1.M8(VIOIN_18)
RADAR_1V_RF_OUT: U1.L3(VDDA_10RF) U1.M3(VDDA_10RF)
RADAR_3V3: R4.1 R73.1 R74.1 R75.1 R165.2 U1.G12(VIOIN) U1.M11(VIOIN)
RADAR_VBGAP: U1.H5(VBGAP)
VPP_1P7: C31.2 U1.A8(VPP)
DCA_LP_HOST_INTR_GPIO_0_LED: U1.J10(GPIO_5) ; port DCA_LP_HOST_INTR_GPIO_0_LED
DCA_LP_SPI_CLK_I2C_SCL: R75.2 U1.D10(SPIA_CLK) ; port DCA_LP_SPI_CLK_I2C_SCL
DCA_LP_SPI_CS_I2C_SDA: R4.2 U1.D11(~{SPIA_cs0}) ; port DCA_LP_SPI_CS_I2C_SDA
DCA_LP_SPI_MISO_REG_MODE: U1.C11(SPIA_MISO) ; port DCA_LP_SPI_MISO_REG_MODE
DCA_LP_SPI_MOSI: U1.B12(SPIA_MOSI) ; port DCA_LP_SPI_MOSI
GPADC1: C3.1 R86.2 U1.M6(ADC1)
GPADC2: C78.1 R89.2 U1.L6(ADC2)
LVDS_D0_LIN_PHY_RX: U1.H10(GPIO_2) ; port LVDS_D0_LIN_PHY_RX
LVDS_D1_XDS_UARTA_RX_CAN_RX: U1.J11(UARTA_RX) ; port LVDS_D1_XDS_UARTA_RX_CAN_RX
LVDS_D2_XDS_UARTA_TX_CAN_TX: U1.L12(UARTA_TX) ; port LVDS_D2_XDS_UARTA_TX_CAN_TX
LVDS_FRCLK_HOST_CLK_TP: U1.M10(HOST_CLK_REQ) ; port LVDS_FRCLK_HOST_CLK_TP
PMIC_CLKOUT_LIN_PHY_TX_SOP1: U1.H11(PMIC_CLKOUT) ; port PMIC_CLKOUT_LIN_PHY_TX_SOP1
QSPI_CS: U1.A10(~{QSPI_CS}) ; port QSPI_CS
QSPI_D0: U1.B11(QSPI[0]) ; port QSPI_D0
QSPI_D1: U1.B8(QSPI[1]) ; port QSPI_D1
QSPI_D2: U1.B10(QSPI[2]) ; port QSPI_D2
QSPI_D3: U1.B9(QSPI[3]) ; port QSPI_D3
QSPI_SCLK: U1.A11(QSPI_CLK) ; port QSPI_SCLK
RADAR_NRST: C53.2 R165.1 U1.L10(~{RESET}) ; port RADAR_NRST
RADAR_OSC_CLKOUT: TP5.1 U1.A7(OSC_CLK_OUT)
RX1: U1.K1(RX1) ; port RX1
RX2: U1.H1(RX2) ; port RX2
RX3: U1.F1(RX3) ; port RX3
TX1: U1.A3(TX1) ; port TX1
TX2: U1.A5(TX2) ; port TX2
XDS_DCA_LP_RS232_RX: R74.2 U1.F11(RS232_RX) ; port XDS_DCA_LP_RS232_RX
XDS_DCA_LP_RS232_TX: R73.2 U1.E10(RS232_TX) ; port XDS_DCA_LP_RS232_TX
XDS_DCA_TCK: U1.C12(TCK) ; port XDS_DCA_TCK
XDS_DCA_TDI: U1.G11(TDI) ; port XDS_DCA_TDI
XDS_DCA_TDO_SOP0: R93.1 ; port XDS_DCA_TDO_SOP0
XDS_DCA_TMS: U1.E12(TMS) ; port XDS_DCA_TMS
XTALM: C33.2 U1.B1(CLKM) Y1.1(1_Xtal) ; port XTALM
XTALP: C32.2 U1.D1(CLKP) Y1.3(2_Xtal) ; port XTALP
NetR67_1: R67.1 R89.1 R131.2
NetR93_2: R93.2 U1.E11(TDO)

Not connected (* = marked no-connect by the designer): U1 K11(~{ERROR_OUT})* L11(UARTA_RTS)*

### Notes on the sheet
- xWRL6432 CHIP
- 1. Antenna traces are GCPW traces
- 2. 'Generic No ERCs' were placed intentionally on Single Port RF Tx, Rx lines
- Design Note:
- CAD Note: Place C3 and C78 close to xWRL6432 IC
- 40 MHz CRYSTAL OSCILLATOR
- RESET
- Alternate Crystal part number : CX2016SA40000D0PTWC1

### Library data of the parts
C3 C78 = CMP-0009692-3: CAP, CERM, 1 uF, 6.3 V, +/- 20%, X5R, 0201; Manufacturer: MuRata; TaMin_C: -55°C; Polarized: N; SizeAreaWB_mm2: 2.08; Value1: Unknown; U/M: EA; Value: 1uF; TaMax_C: 85°C; SizeZ_mm: 0.33; SizeX_mm: 0.6; SizeY_mm: 0.3; Cap_Case: 0201; SizeArea_mm2: 0.18; Cap_F: 1µF; AEC Category: Q200
C31 C53 = CMP-0064969-1: CAP, CERM, 0.1 uF, 10 V,+/- 10%, X7S, 0201; Manufacturer: MuRata; TaMin_C: -55°C; Polarized: N; SizeAreaWB_mm2: 2.08; Value1: Unknown; U/M: EA; Value: 0.1uF; TaMax_C: 125°C; SizeZ_mm: 0.26; SizeX_mm: 0.6; SizeY_mm: 0.3; SizeArea_mm2: 0.18; Cap_F: 100nF; AEC Category: Q200
C32 C33 = CMP-0006367-2: CAP, CERM, 4.7 pF, 50 V, +/- 2%, C0G/NP0, 0402; Manufacturer: MuRata; TaMin_C: -55°C; Polarized: N; SizeAreaWB_mm2: 3; Value1: Unknown; U/M: EA; Value: 4.7pF; TaMax_C: 125°C; SizeZ_mm: 0.6; SizeX_mm: 1; SizeY_mm: 0.5; Cap_Case: 0402; Value2: 50V; AEC Category: Q200
R4 R73-R75 = CMP-0026245-2: RES, 2.00 M, 1%, 0.063 W, AEC-Q200 Grade 0, 0402; Manufacturer: Vishay-Dale; Power_W: 63mW; TempCo: 100 ppm/C; Value_Code: 2M00; Value: 2.00Meg; EIA_Code: E96; Res_ohm: 2M; SizeX_mm: 1; SizeY_mm: 0.5; SizeZ_mm: 0.6; Value2: 0.063W; AEC Qualified: Y; VDC_V: 50V; AEC Category: Q200; AEC Grade: 0
R67 R131 R165 = CMP-0095015-1: Res Thick Film 0201 10K Ohm 0.5% 0.05W ±50ppm/°C Molded SMD Pressed Carrier T/R; Manufacturer: Panasonic; SizeZ_mm: 0.26mm; AEC Qualified: No; VDC_V: 15V; Power_W: 50mW
R86 R89 = CMP-0027267-3: RES, 1.00 k, 1%, 0.05 W, 0201; Manufacturer: Vishay-Dale; Power_W: 50mW; TempCo: 100 ppm/C; Value_Code: 1k00; Value: 1.00k; EIA_Code: E96; Res_ohm: 1k; SizeX_mm: 0.6; SizeY_mm: 0.3; SizeZ_mm: 0.26; Value2: 0.05W; SizeArea_mm2: 0.18; AEC Qualified: N; VDC_V: 30V; AEC Category: Q200
R93 = CMP-0027275-3: RES, 33.2, 1%, 0.05 W, 0201; Manufacturer: Vishay-Dale; Power_W: 50mW; TempCo: 200 ppm/C; Value_Code: 33R2; Value: 33.2; EIA_Code: E96; SizeX_mm: 0.6; SizeY_mm: 0.3; SizeZ_mm: 0.26; Value2: 0.05W; SizeArea_mm2: 0.18; AEC Qualified: N; AEC Category: Q200
TP5 = CMP-0078143-4: TEST POINT.  No entry in BOM.
U1 = CMP-0095272-2: Manufacturer: Texas Instruments; SizeZ_mm: 0.97mm; Standoff Height: 0.15mm; CompType: IC; AEC Category: Q200
Y1 = CMP-0090505-1: 40MHz ±10ppm Crystal 8pF 50 Ohms 4-SMD, No Lead; Manufacturer: Diodes; Frequency Stability: 50ppm; Esr: 50; AEC Qualified: Yes; AEC Grade: Grade 1; SizeZ_mm: 0.55mm

## Sheet PROC198_Decoupling_caps.SchDoc: DECOUPLING_CAPS
size 431 x 279 mm; Date: Not shown in title block; ApprovedBy: Not shown in title block; CheckedBy: Not shown in title block; Author: Not shown in title block; CompanyName: Not shown in title block; DrawnBy: Justin Yin; Engineer: Not shown in title block; Organization: Not shown in title block; Address1: Not shown in title block; Address2: Not shown in title block; Address3: Not shown in title block; Address4: Not shown in title block; DocumentNumber: 6; Revision: Use project parameter SCH_Rev; SheetNumber: 6; SheetTotal: 8; PageSetup: Record=PageOptions¦CenterHorizontal=True¦CenterVertical=True¦PrintScale=1.00¦XCorrection=1.00¦YCorrection=1.00¦PrintKind=0¦BorderSize=5000000¦LeftOffset=0¦BottomOffset=0¦Orientation=2¦PaperLength=1000¦PaperWidth=1000¦Scale=100¦PaperSource=15¦PrintQuality=600¦MediaType=1¦DitherType=10¦PaperKind=Letter¦PrintScaleMode=1
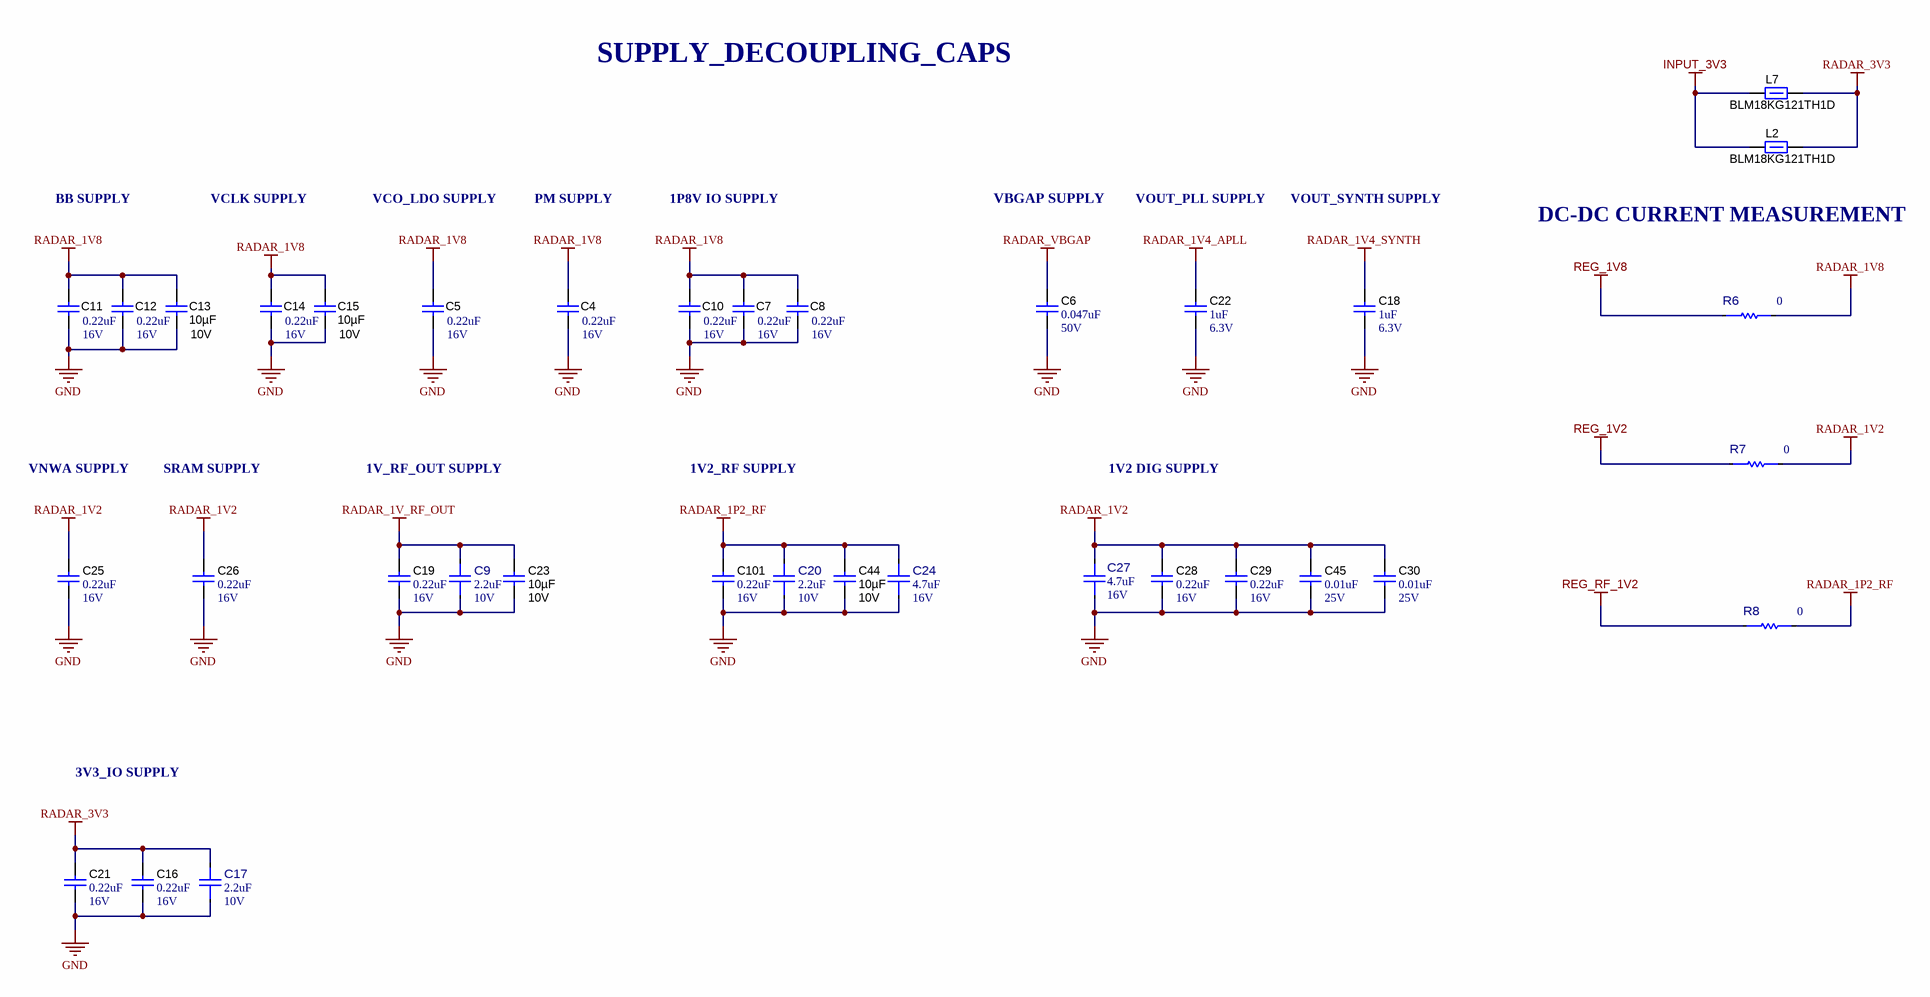
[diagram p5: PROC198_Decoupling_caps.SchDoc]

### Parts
C4  VDC_V: 16V  ValueDisplayed: 0.22uF  [0402L]  (hidden comment: GRM155R71C224KA12D)
C5  VDC_V: 16V  ValueDisplayed: 0.22uF  [0402L]  (hidden comment: GRM155R71C224KA12D)
C6  VDC_V: 50V  ValueDisplayed: 0.047uF  [0402L]  (hidden comment: C1005X7R1H473K050BB)
C7  VDC_V: 16V  ValueDisplayed: 0.22uF  [0402L]  (hidden comment: GRM155R71C224KA12D)
C8  VDC_V: 16V  ValueDisplayed: 0.22uF  [0402L]  (hidden comment: GRM155R71C224KA12D)
C9  ValueDisplayed: 2.2uF  VDC_V: 10V  [FP-GRM155R61A225ME01D_0402-MFG]  (hidden comment: GRM155R61A225ME01D)
C10  VDC_V: 16V  ValueDisplayed: 0.22uF  [0402L]  (hidden comment: GRM155R71C224KA12D)
C11  VDC_V: 16V  ValueDisplayed: 0.22uF  [0402L]  (hidden comment: GRM155R71C224KA12D)
C12  VDC_V: 16V  ValueDisplayed: 0.22uF  [0402L]  (hidden comment: GRM155R71C224KA12D)
C13  Value2: 10V  Cap_F: 10µF  [0603L]  (hidden comment: GRM188Z71A106MA73D)
C14  VDC_V: 16V  ValueDisplayed: 0.22uF  [0402L]  (hidden comment: GRM155R71C224KA12D)
C15  Value2: 10V  Cap_F: 10µF  [0603L]  (hidden comment: GRM188Z71A106MA73D)
C16  VDC_V: 16V  ValueDisplayed: 0.22uF  [0402L]  (hidden comment: GRM155R71C224KA12D)
C17  ValueDisplayed: 2.2uF  VDC_V: 10V  [FP-GRM155R61A225ME01D_0402-MFG]  (hidden comment: GRM155R61A225ME01D)
C18  VDC_V: 6.3V  ValueDisplayed: 1uF  [0402S]  (hidden comment: GRM155R70J105KA12D)
C19  VDC_V: 16V  ValueDisplayed: 0.22uF  [0402L]  (hidden comment: GRM155R71C224KA12D)
C20  ValueDisplayed: 2.2uF  VDC_V: 10V  [FP-GRM155R61A225ME01D_0402-MFG]  (hidden comment: GRM155R61A225ME01D)
C21  VDC_V: 16V  ValueDisplayed: 0.22uF  [0402L]  (hidden comment: GRM155R71C224KA12D)
C22  VDC_V: 6.3V  ValueDisplayed: 1uF  [0402S]  (hidden comment: GRM155R70J105KA12D)
C23  Value2: 10V  Cap_F: 10µF  [0603L]  (hidden comment: GRM188Z71A106MA73D)
C24  ValueDisplayed: 4.7uF  VDC_V: 16V  [FP-GRM188C71C475KE21D_0603-MFG]  (hidden comment: GRM188C71C475KE21D)
C25  VDC_V: 16V  ValueDisplayed: 0.22uF  [0402L]  (hidden comment: GRM155R71C224KA12D)
C26  VDC_V: 16V  ValueDisplayed: 0.22uF  [0402L]  (hidden comment: GRM155R71C224KA12D)
C27  ValueDisplayed: 4.7uF  VDC_V: 16V  [FP-GRM188C71C475KE21D_0603-MFG]  (hidden comment: GRM188C71C475KE21D)
C28  VDC_V: 16V  ValueDisplayed: 0.22uF  [0402L]  (hidden comment: GRM155R71C224KA12D)
C29  VDC_V: 16V  ValueDisplayed: 0.22uF  [0402L]  (hidden comment: GRM155R71C224KA12D)
C30  VDC_V: 25V  ValueDisplayed: 0.01uF  [0402L]  (hidden comment: GRM155R71E103KA01D)
C44  Value2: 10V  Cap_F: 10µF  [0603L]  (hidden comment: GRM188Z71A106MA73D)
C45  VDC_V: 25V  ValueDisplayed: 0.01uF  [0402L]  (hidden comment: GRM155R71E103KA01D)
C101  VDC_V: 16V  ValueDisplayed: 0.22uF  [0402L]  (hidden comment: GRM155R71C224KA12D)
L2  BLM18KG121TH1D  [0603L]
L7  BLM18KG121TH1D  [0603L]
R6  Res_ohm: 0  [FP-ERJ-3GEY0R00V_0603-MFG]  (hidden comment: ERJ-3GEY0R00V)
R7  Res_ohm: 0  [FP-ERJ-3GEY0R00V_0603-MFG]  (hidden comment: ERJ-3GEY0R00V)
R8  Res_ohm: 0  [FP-ERJ-3GEY0R00V_0603-MFG]  (hidden comment: ERJ-3GEY0R00V)

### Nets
GND: C4.2 C5.2 C6.2 C7.2 C8.2 C9.1 C10.2 C11.2 C12.2 C13.2 C14.2 C15.2 C16.2 C17.1 C18.2 C19.2 C20.1 C21.2 C22.2 C23.2 C24.1 C25.2 C26.2 C27.1 C28.2 C29.2 C30.2 C44.2 C45.2 C101.2
INPUT_3V3: L2.1 L7.1
RADAR_1P2_RF: C20.2 C24.2 C44.1 C101.1 R8.2
RADAR_1V2: C25.1 C26.1 C27.2 C28.1 C29.1 C30.1 C45.1 R7.2
RADAR_1V4_APLL: C22.1
RADAR_1V4_SYNTH: C18.1
RADAR_1V8: C4.1 C5.1 C7.1 C8.1 C10.1 C11.1 C12.1 C13.1 C14.1 C15.1 R6.2
RADAR_1V_RF_OUT: C9.2 C19.1 C23.1
RADAR_3V3: C16.1 C17.2 C21.1 L2.2 L7.2
RADAR_VBGAP: C6.1
REG_1V2: R7.1
REG_1V8: R6.1
REG_RF_1V2: R8.1

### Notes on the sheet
- SUPPLY_DECOUPLING_CAPS
- BB SUPPLY
- VCLK SUPPLY
- VCO_LDO SUPPLY
- PM SUPPLY
- 1P8V IO SUPPLY
- VBGAP SUPPLY
- VOUT_PLL SUPPLY
- VOUT_SYNTH SUPPLY
- DC-DC CURRENT MEASUREMENT
- VNWA SUPPLY
- SRAM SUPPLY
- 1V_RF_OUT SUPPLY
- 1V2_RF SUPPLY
- 1V2 DIG SUPPLY
- 3V3_IO SUPPLY

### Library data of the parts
C4 C5 C7 C8 C10-C12 C14 C16 C19 C21 C25 C26 C28 C29 C101 = CMP-0006648-2: CAP, CERM, 0.22 uF, 16 V, +/- 10%, X7R, 0402; Manufacturer: MuRata; TaMin_C: -55°C; Polarized: N; SizeAreaWB_mm2: 3; Value1: Unknown; U/M: EA; Value: 0.22uF; TaMax_C: 125°C; SizeZ_mm: 0.6; SizeX_mm: 1; SizeY_mm: 0.5; Cap_Case: 0402; Cap_F: 220nF; AEC Category: Q200
C6 = CMP-0006298-2: CAP, CERM, 0.047 uF, 50 V, +/- 10%, X7R, 0402; Manufacturer: TDK; TaMin_C: -55°C; ESR_ohm: 0.06407; Polarized: N; SizeAreaWB_mm2: 3; Value1: 0.06407 ohm; U/M: EA; SizeZ_mm: 0.6; SizeX_mm: 1; SizeY_mm: 0.5; Cap_Case: 0402; Cap_F: 47nF; IRMS_A: 6.46122dA; AEC Category: Q200; TaMax_C: 125°C
C9 C17 C20 = CMP-0097887-1: Chip Multilayer Ceramic Capacitors for General Purpose, 0402, 2.2uF, X5R, 15%, 20%, 10V; Manufacturer: Murata; SizeZ_mm: 0.55mm; Value: 2.2µF; AEC Qualified: No
C13 C15 C23 C44 = CMP-0007497-5: as C56 on sheet PROC198_DC_Regulators
C18 C22 = CMP-0064947-2: CAP, CERM, 1 uF, 6.3 V,+/- 10%, X7R, 0402; Manufacturer: MuRata; TaMin_C: -55°C; Polarized: N; SizeAreaWB_mm2: 3; Value1: Unknown; U/M: EA; Value: 1uF; TaMax_C: 125°C; SizeZ_mm: 0.6; SizeX_mm: 1; SizeY_mm: 0.5; Cap_Case: 0402; Cap_F: 1µF; AEC Category: Q200
C24 C27 = CMP-0097886-1: Chip Multilayer Ceramic Capacitors for General Purpose, 0603, 4.7uF, X7S, 22%, 10%, 16V; Manufacturer: Murata; AEC Qualified: No; Value: 4.7µF; SizeZ_mm: 1mm
C30 C45 = CMP-0006658-2: CAP, CERM, 0.01 uF, 25 V, +/- 10%, X7R, 0402; Manufacturer: MuRata; TaMin_C: -55°C; Polarized: N; SizeAreaWB_mm2: 3; Value1: Unknown; U/M: EA; Value: 0.01uF; TaMax_C: 125°C; SizeZ_mm: 0.6; SizeX_mm: 1; SizeY_mm: 0.5; Cap_Case: 0402; Cap_F: 10nF; AEC Category: Q200
L2 L7 = CMP-0077879-2: Ferrite Bead, 120 ohm @ 100 MHz, 1.9 A, 0603; Manufacturer: MuRata; ZTyp@100MHz_Ohm: 120; SizeAreaWB_mm2: 4.68; DCR_ohm: 0.04; Value1: 0.04 ohm; Value: 120 ohm; Imax_A: 1.9A; SizeZ_mm: 1.0; SizeX_mm: 1.6; SizeY_mm: 0.8; SizeArea_mm2: 1.28
R6-R8 = CMP-0089143-1: 0 Ohms Jumper 0.1W, 1/10W Chip Resistor 0603 (1608 Metric) Automotive AEC-Q200 Thick Film; Manufacturer: Panasonic; SizeZ_mm: 0.55mm; AEC Grade: Grade 0; VDC_V: 75V; TempCo: -100/+600ppm/°C; AEC Qualified: Yes; Power_W: 100mW; Tolerance_%: 5%

## Sheet PROC198_QSPI_Flash.SchDoc: QSPI_FLASH
size 431 x 279 mm; Date: Not shown in title block; ApprovedBy: Not shown in title block; CheckedBy: Not shown in title block; Author: Not shown in title block; CompanyName: Not shown in title block; DrawnBy: Justin Yin; Engineer: Not shown in title block; Organization: Not shown in title block; Address1: Not shown in title block; Address2: Not shown in title block; Address3: Not shown in title block; Address4: Not shown in title block; DocumentNumber: 7; Revision: Use project parameter SCH_Rev; SheetNumber: 7; SheetTotal: 8; PageSetup: Record=PageOptions¦CenterHorizontal=True¦CenterVertical=True¦PrintScale=1.00¦XCorrection=1.00¦YCorrection=1.00¦PrintKind=0¦BorderSize=5000000¦LeftOffset=0¦BottomOffset=0¦Orientation=2¦PaperLength=1000¦PaperWidth=1000¦Scale=100¦PaperSource=15¦PrintQuality=600¦MediaType=1¦DitherType=10¦PaperKind=Letter¦PrintScaleMode=1
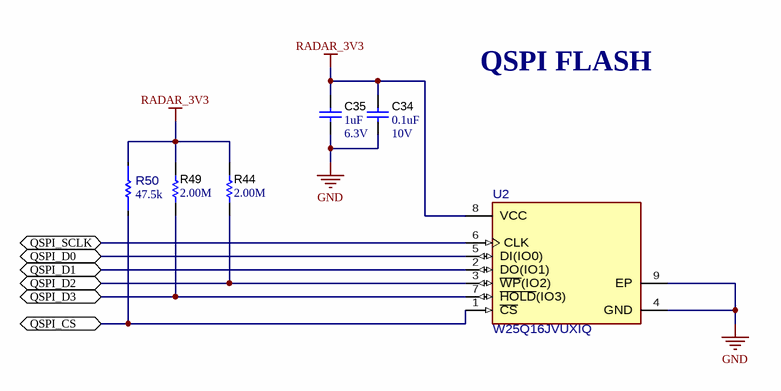
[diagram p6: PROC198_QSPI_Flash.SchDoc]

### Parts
C34  Value2: 10V  ValueDisplayed: 0.1uF  [0201]  (hidden comment: GRM033C71A104KE14D)
C35  VDC_V: 6.3V  ValueDisplayed: 1uF  [0402L]  (hidden comment: GRM155R70J105KA12D)
R44  ValueDisplayed: 2.00M  [0402]  (hidden comment: CRCW04022M00FKED)
R49  ValueDisplayed: 2.00M  [0402]  (hidden comment: CRCW04022M00FKED)
R50  Res_ohm: 47.5k  [FP-AC0402FR-0747K5L_0402-MFG]  (hidden comment: AC0402FR-0747K5L)
U2  W25Q16JVUXIQ  [FP-W25Q16JVUXIQ_USON8-MFG]

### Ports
QSPI_CS (bidir), QSPI_D0 (bidir), QSPI_D1 (bidir), QSPI_D2 (bidir), QSPI_D3 (bidir), QSPI_SCLK (bidir)

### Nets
GND: C34.1 C35.2 U2.4(GND) U2.9(EP)
RADAR_3V3: C34.2 C35.1 R44.2 R49.2 R50.1 U2.8(VCC)
QSPI_CS: R50.2 U2.1(~{CS}) ; port QSPI_CS
QSPI_D0: U2.5(DI(IO0)) ; port QSPI_D0
QSPI_D1: U2.2(DO(IO1)) ; port QSPI_D1
QSPI_D2: R44.1 U2.3(~{WP}(IO2)) ; port QSPI_D2
QSPI_D3: R49.1 U2.7(~{HOLD}(IO3)) ; port QSPI_D3
QSPI_SCLK: U2.6(CLK) ; port QSPI_SCLK

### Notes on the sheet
- QSPI FLASH

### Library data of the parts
C34 = CMP-0064969-1: as C31 on sheet PROC198_xWRL6432_Chip
C35 = CMP-0064947-2: as C18 on sheet PROC198_Decoupling_caps
R44 R49 = CMP-0026245-2: as R4 on sheet PROC198_xWRL6432_Chip
R50 = CMP-0095013-1: Res Thick Film 0402 47.5K Ohm 1% 1/16W ±100ppm/°C Molded SMD Paper T/R; Manufacturer: Yageo; VDC_V: 50V; SizeZ_mm: 0.37mm; AEC Grade: Grade 0; Power_W: 62.5mW; AEC Qualified: Yes
U2 = CMP-0097318-1: FLASH - NOR Memory IC 16Mb (2M x 8) SPI - Quad I/O 133 MHz 6 ns 8-USON (2x3); Manufacturer: Winbond; Max Supply Voltage: 3.6V; Min Supply Voltage: 2.7V; Frequency_Fixed: 532MHz; AEC Qualified: No; SizeZ_mm: 0.6mm; Access Time: 6ns; TaMax_C: +85°C; Standoff Height: 0mm; Nominal Supply Current: 2-20mA; TaMin_C: -40°C; Memory Size: 16Mbits

## Sheet PROC198_Hardware.SchDoc: HARDWARE
size 431 x 279 mm; Date: Not shown in title block; ApprovedBy: Not shown in title block; CheckedBy: Not shown in title block; Author: Not shown in title block; CompanyName: Not shown in title block; DrawnBy: Justin Yin; Engineer: Not shown in title block; Organization: Not shown in title block; Address1: Not shown in title block; Address2: Not shown in title block; Address3: Not shown in title block; Address4: Not shown in title block; DocumentNumber: 8; Revision: Use project parameter SCH_Rev; SheetNumber: 8; SheetTotal: 8; PageSetup: Record=PageOptions¦CenterHorizontal=True¦CenterVertical=True¦PrintScale=1.00¦XCorrection=1.00¦YCorrection=1.00¦PrintKind=0¦BorderSize=5000000¦LeftOffset=0¦BottomOffset=0¦Orientation=2¦PaperLength=1000¦PaperWidth=1000¦Scale=100¦PaperSource=15¦PrintQuality=600¦MediaType=1¦DitherType=10¦PaperKind=Letter¦PrintScaleMode=1
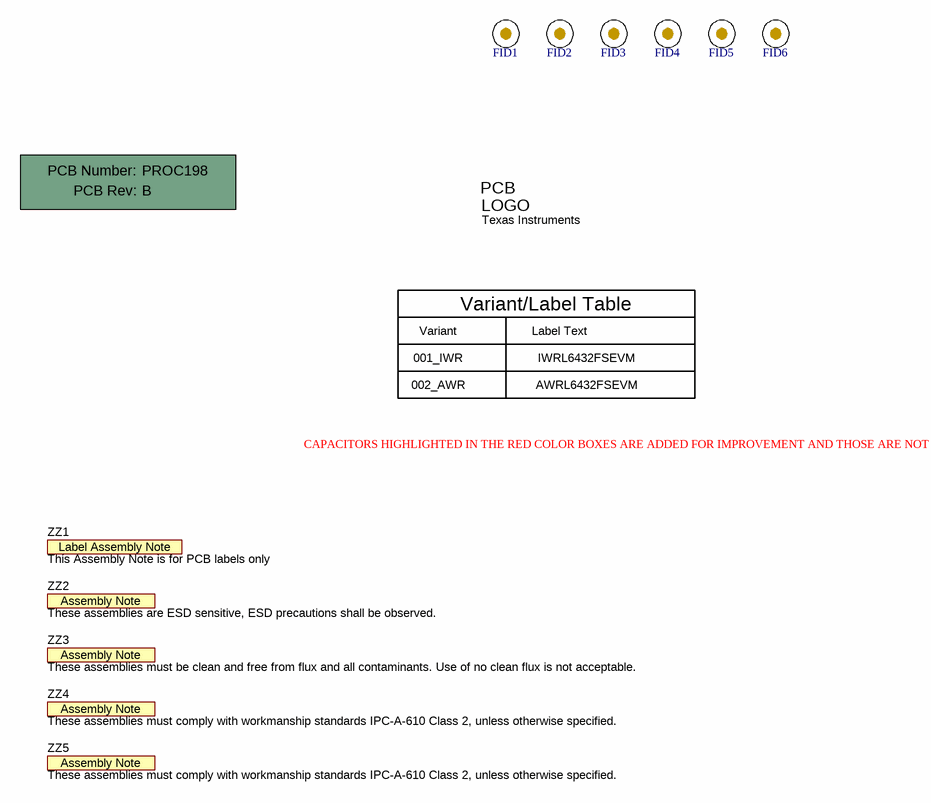
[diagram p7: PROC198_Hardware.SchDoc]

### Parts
!PCB  Printed Circuit Board  (value not drawn)  (mechanical)
FID1  Fiducial  [Fiducial10-20]  (value not drawn)
FID2  Fiducial  [Fiducial10-20]  (value not drawn)
FID3  Fiducial  [Fiducial10-20]  (value not drawn)
FID4  Fiducial  [Fiducial10-20]  (value not drawn)
FID5  Fiducial  [Fiducial10-20]  (value not drawn)
FID6  Fiducial  [Fiducial10-20]  (value not drawn)
Logo1  Texas Instruments  [TI_Stacked_Overlay_Small]  (no BOM)
ZZ1  This Assembly Note is for PCB labels only  [AssemblyNoteLabel]  (no BOM)
ZZ2  These assemblies are ESD sensitive, ESD precautions shall be observed.  [AssemblyNote]  (no BOM)
ZZ3  These assemblies must be clean and free from flux and all contaminants. Use of no clean flux is not acceptable.  [AssemblyNote]  (no BOM)
ZZ4  These assemblies must comply with workmanship standards IPC-A-610 Class 2, unless otherwise specified.  [AssemblyNote]  (no BOM)
ZZ5  These assemblies must comply with workmanship standards IPC-A-610 Class 2, unless otherwise specified.  [AssemblyNote]  (no BOM)

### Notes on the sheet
- Variant
- 001_IWR
- Variant/Label Table
- Label Text
- IWRL6432FSEVM
- 002_AWR
- AWRL6432FSEVM
- CAPACITORS HIGHLIGHTED IN THE RED COLOR BOXES ARE ADDED FOR IMPROVEMENT AND THOSE ARE NOT MANDITORY.

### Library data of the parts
!PCB = CMP-0003618-2: Manufacturer: Any; PartNumber: PROC198
FID1-FID6 = CMP-0077181-1: Fiducial mark.  There is nothing to buy or mount.
Logo1 = CMP-0074838-1: Texas Instrument Corporate Signature; SymbolCreator: a0412235; Lib Reference: TI_Logo
ZZ1 = CMP-0003616-3
ZZ2 = CMP-0077236-1
ZZ3 = CMP-0077237-1
ZZ4 ZZ5 = CMP-0077238-1

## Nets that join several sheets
GND: PROC198_PWR_Connector (5 pins), PROC198_DC_Regulators (26 pins), PROC198_xWRL6432_Chip (49 pins), PROC198_Decoupling_caps (30 pins), PROC198_QSPI_Flash (C34.1 C35.2 U2.4 U2.9)
INPUT_3V3: PROC198_PWR_Connector (J1.1 J1.2 J1.4), PROC198_DC_Regulators (14 pins), PROC198_Decoupling_caps (L2.1 L7.1)
RADAR_1P2_RF: PROC198_xWRL6432_Chip (U1.L4 U1.M4), PROC198_Decoupling_caps (5 pins)
RADAR_1V2: PROC198_xWRL6432_Chip (9 pins), PROC198_Decoupling_caps (8 pins)
RADAR_1V4_APLL: PROC198_xWRL6432_Chip (U1.G5), PROC198_Decoupling_caps (C22.1)
RADAR_1V4_SYNTH: PROC198_xWRL6432_Chip (U1.D3), PROC198_Decoupling_caps (C18.1)
RADAR_1V8: PROC198_xWRL6432_Chip (10 pins), PROC198_Decoupling_caps (11 pins)
RADAR_1V_RF_OUT: PROC198_xWRL6432_Chip (U1.L3 U1.M3), PROC198_Decoupling_caps (C9.2 C19.1 C23.1)
RADAR_3V3: PROC198_DC_Regulators (R175.1 TP9.1), PROC198_xWRL6432_Chip (7 pins), PROC198_Decoupling_caps (5 pins), PROC198_QSPI_Flash (6 pins)
RADAR_VBGAP: PROC198_xWRL6432_Chip (U1.H5), PROC198_Decoupling_caps (C6.1)
REG_1V2: PROC198_DC_Regulators (C61.2 L5.2), PROC198_Decoupling_caps (R7.1)
REG_1V8: PROC198_DC_Regulators (C68.2 L6.2), PROC198_Decoupling_caps (R6.1)
REG_RF_1V2: PROC198_DC_Regulators (C79.2 L1.2), PROC198_Decoupling_caps (R8.1)
DCA_LP_HOST_INTR_GPIO_0_LED: PROC198_DC_Regulators (R3.2 R5.2), PROC198_xWRL6432_Chip (U1.J10)
DCA_LP_SPI_CLK_I2C_SCL: PROC198_PWR_Connector (J1.20), PROC198_xWRL6432_Chip (R75.2 U1.D10)
DCA_LP_SPI_CS_I2C_SDA: PROC198_PWR_Connector (J1.17), PROC198_xWRL6432_Chip (R4.2 U1.D11)
DCA_LP_SPI_MISO_REG_MODE: PROC198_PWR_Connector (J1.19), PROC198_xWRL6432_Chip (U1.C11)
DCA_LP_SPI_MOSI: PROC198_PWR_Connector (J1.21), PROC198_xWRL6432_Chip (U1.B12)
LVDS_D0_LIN_PHY_RX: PROC198_PWR_Connector (J1.7), PROC198_xWRL6432_Chip (U1.H10)
LVDS_D1_XDS_UARTA_RX_CAN_RX: PROC198_PWR_Connector (J1.6), PROC198_xWRL6432_Chip (U1.J11)
LVDS_D2_XDS_UARTA_TX_CAN_TX: PROC198_PWR_Connector (J1.8), PROC198_xWRL6432_Chip (U1.L12)
LVDS_FRCLK_HOST_CLK_TP: PROC198_PWR_Connector (J1.10), PROC198_xWRL6432_Chip (U1.M10)
PMIC_CLKOUT_LIN_PHY_TX_SOP1: PROC198_PWR_Connector (J1.5), PROC198_xWRL6432_Chip (U1.H11)
QSPI_CS: PROC198_xWRL6432_Chip (U1.A10), PROC198_QSPI_Flash (R50.2 U2.1)
QSPI_D0: PROC198_xWRL6432_Chip (U1.B11), PROC198_QSPI_Flash (U2.5)
QSPI_D1: PROC198_xWRL6432_Chip (U1.B8), PROC198_QSPI_Flash (U2.2)
QSPI_D2: PROC198_xWRL6432_Chip (U1.B10), PROC198_QSPI_Flash (R44.1 U2.3)
QSPI_D3: PROC198_xWRL6432_Chip (U1.B9), PROC198_QSPI_Flash (R49.1 U2.7)
QSPI_SCLK: PROC198_xWRL6432_Chip (U1.A11), PROC198_QSPI_Flash (U2.6)
RADAR_NRST: PROC198_PWR_Connector (J1.3), PROC198_DC_Regulators (R176.1), PROC198_xWRL6432_Chip (C53.2 R165.1 U1.L10)
XDS_DCA_LP_RS232_RX: PROC198_PWR_Connector (J1.9), PROC198_xWRL6432_Chip (R74.2 U1.F11)
XDS_DCA_LP_RS232_TX: PROC198_PWR_Connector (J1.11), PROC198_xWRL6432_Chip (R73.2 U1.E10)
XDS_DCA_TCK: PROC198_PWR_Connector (J1.14), PROC198_xWRL6432_Chip (U1.C12)
XDS_DCA_TDI: PROC198_PWR_Connector (J1.16), PROC198_xWRL6432_Chip (U1.G11)
XDS_DCA_TDO_SOP0: PROC198_PWR_Connector (J1.15), PROC198_xWRL6432_Chip (R93.1)
XDS_DCA_TMS: PROC198_PWR_Connector (J1.13), PROC198_xWRL6432_Chip (U1.E12)

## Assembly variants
001_IWR: not fitted C2 C3 C78 FID1 FID2 FID3 FID4 FID5 FID6 R2 R3 R5 R67 R86 R89 R121 R131 R179
002_AWR: not fitted C2 C3 C78 FID1 FID2 FID3 FID4 FID5 FID6 R2 R3 R5 R67 R86 R89 R121 R131 R179; alternate parts U1 -> CMP-0095271-2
